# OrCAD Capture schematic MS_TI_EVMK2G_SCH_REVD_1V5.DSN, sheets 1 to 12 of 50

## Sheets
1 50. OVER VOLTAGE PROTECTION: size C; title: OVER VOLTAGE PROTECTION
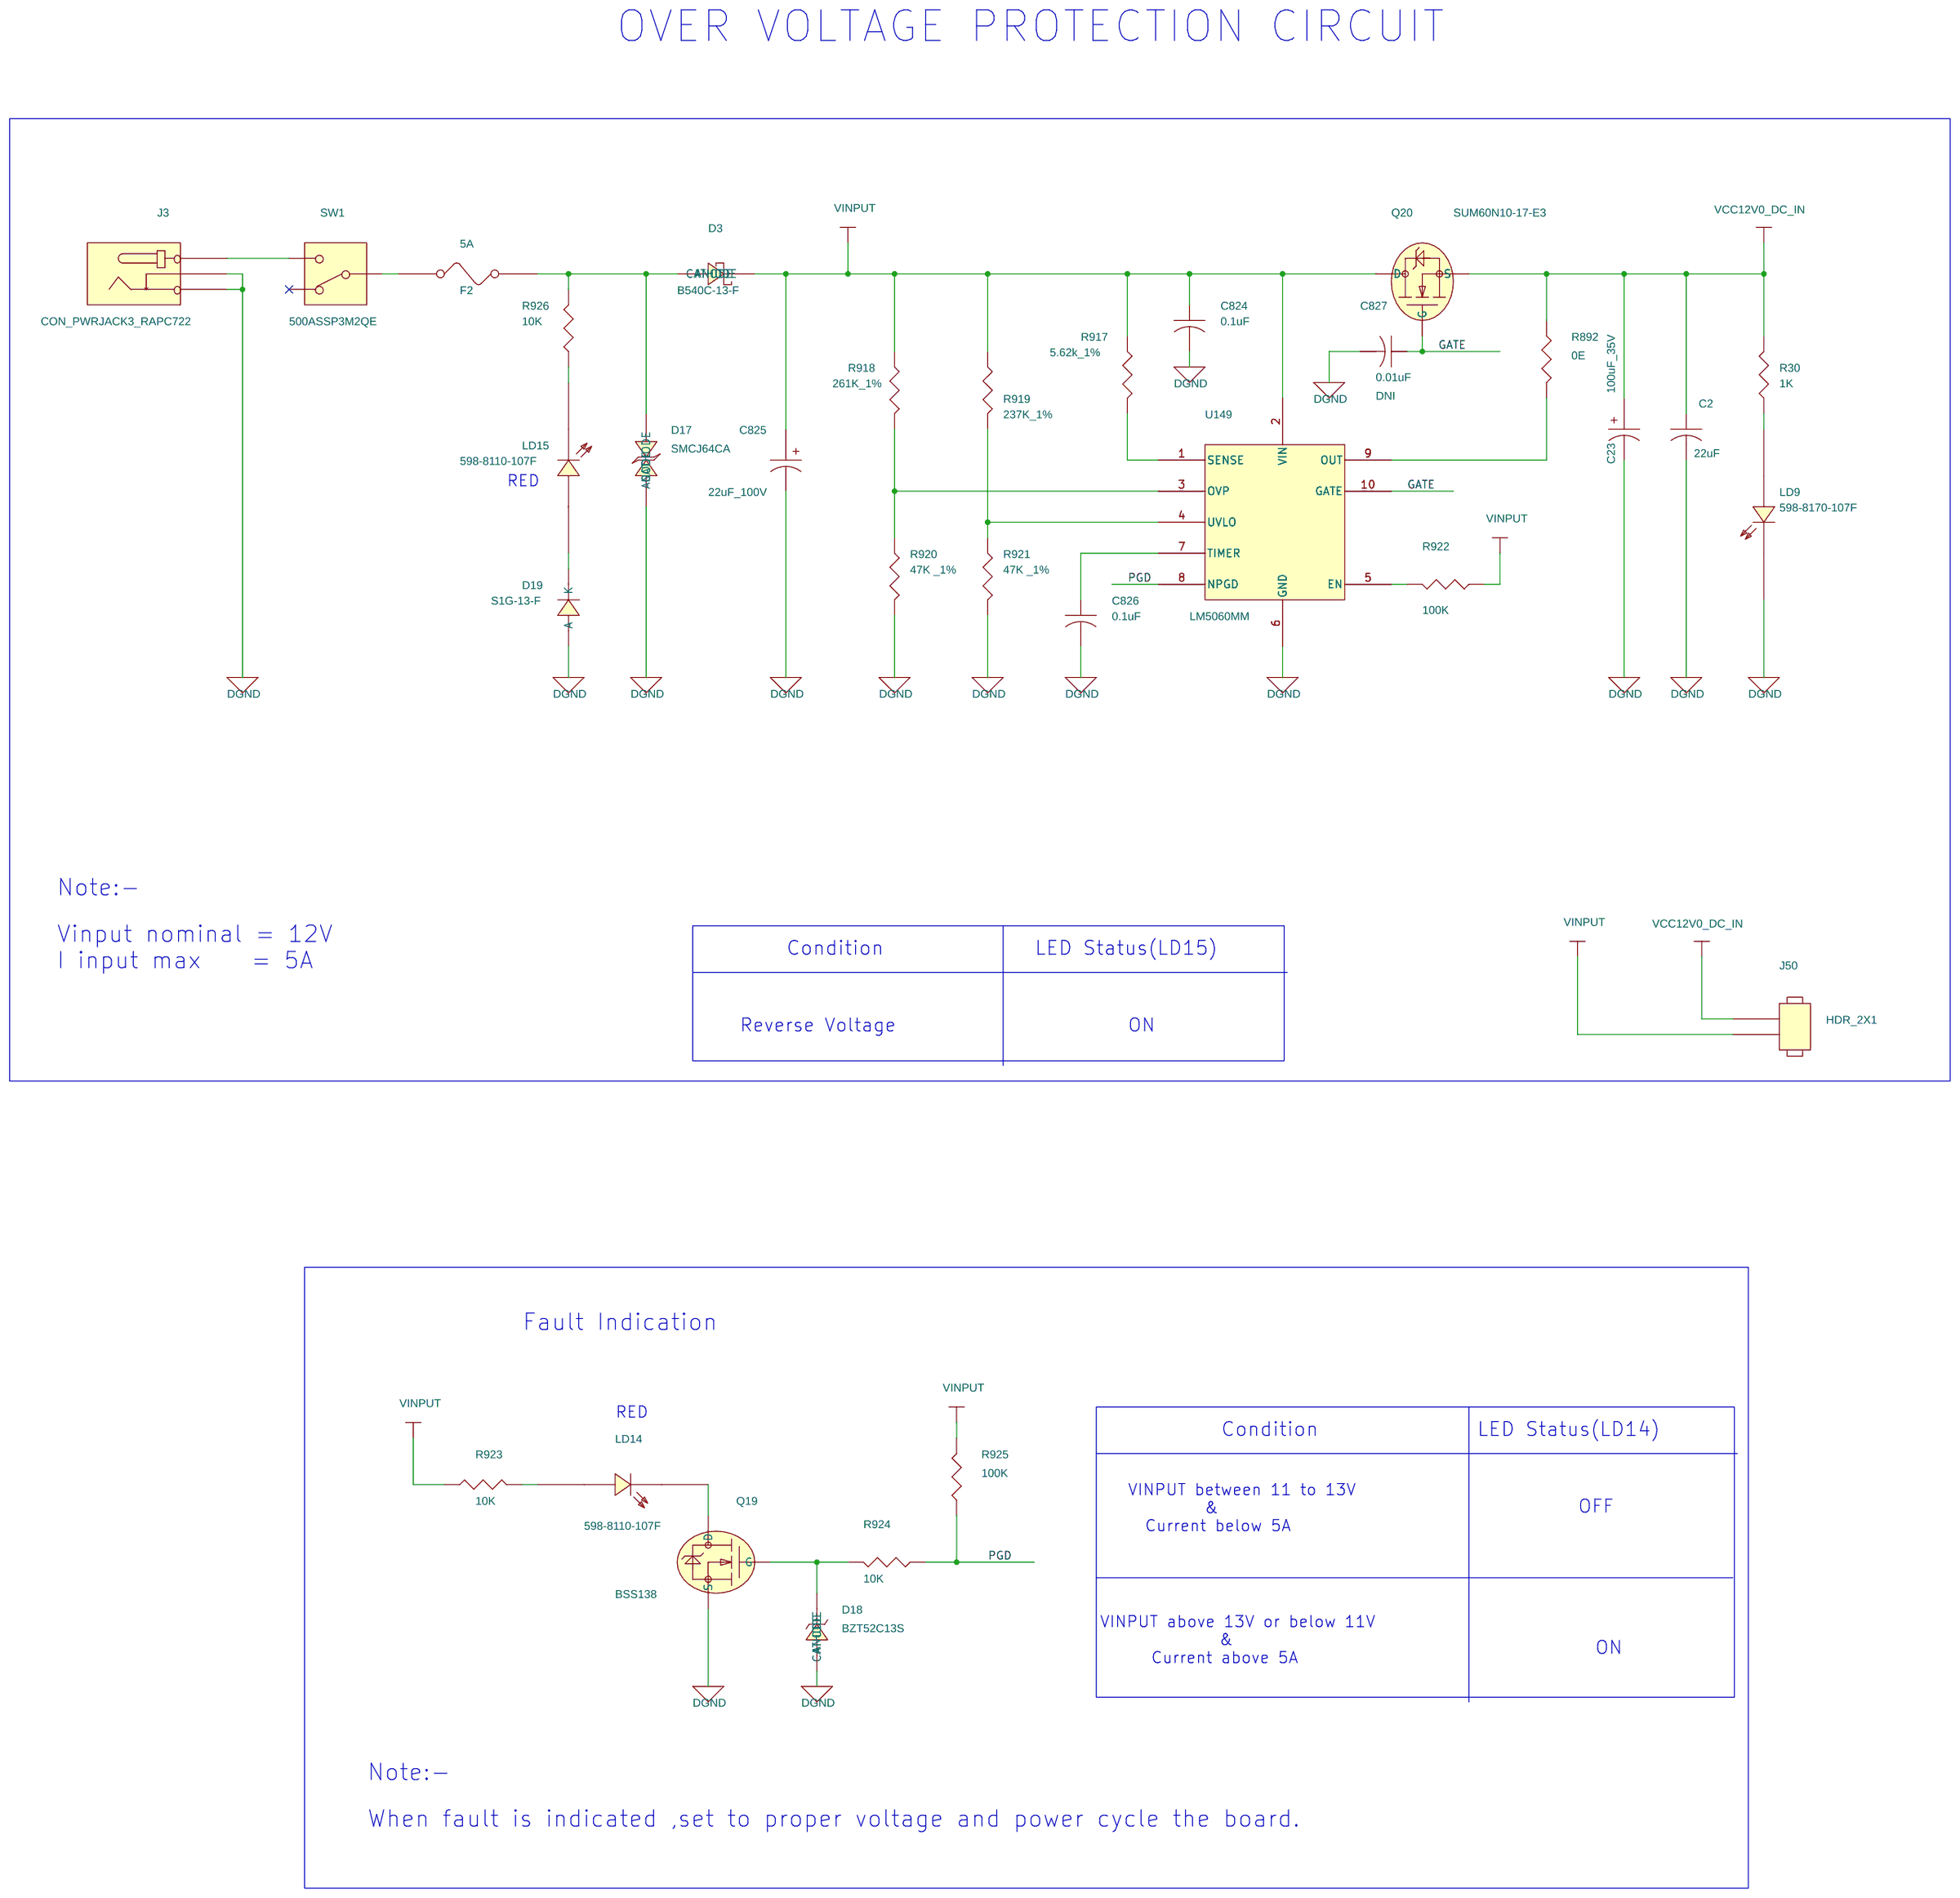
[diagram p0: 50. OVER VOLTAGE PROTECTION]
2 01. TABLE OF CONTENTS: title: TABLE OF CONTENTS; rev: D; note: MS_TI_K2GEVM_SCH_REVD
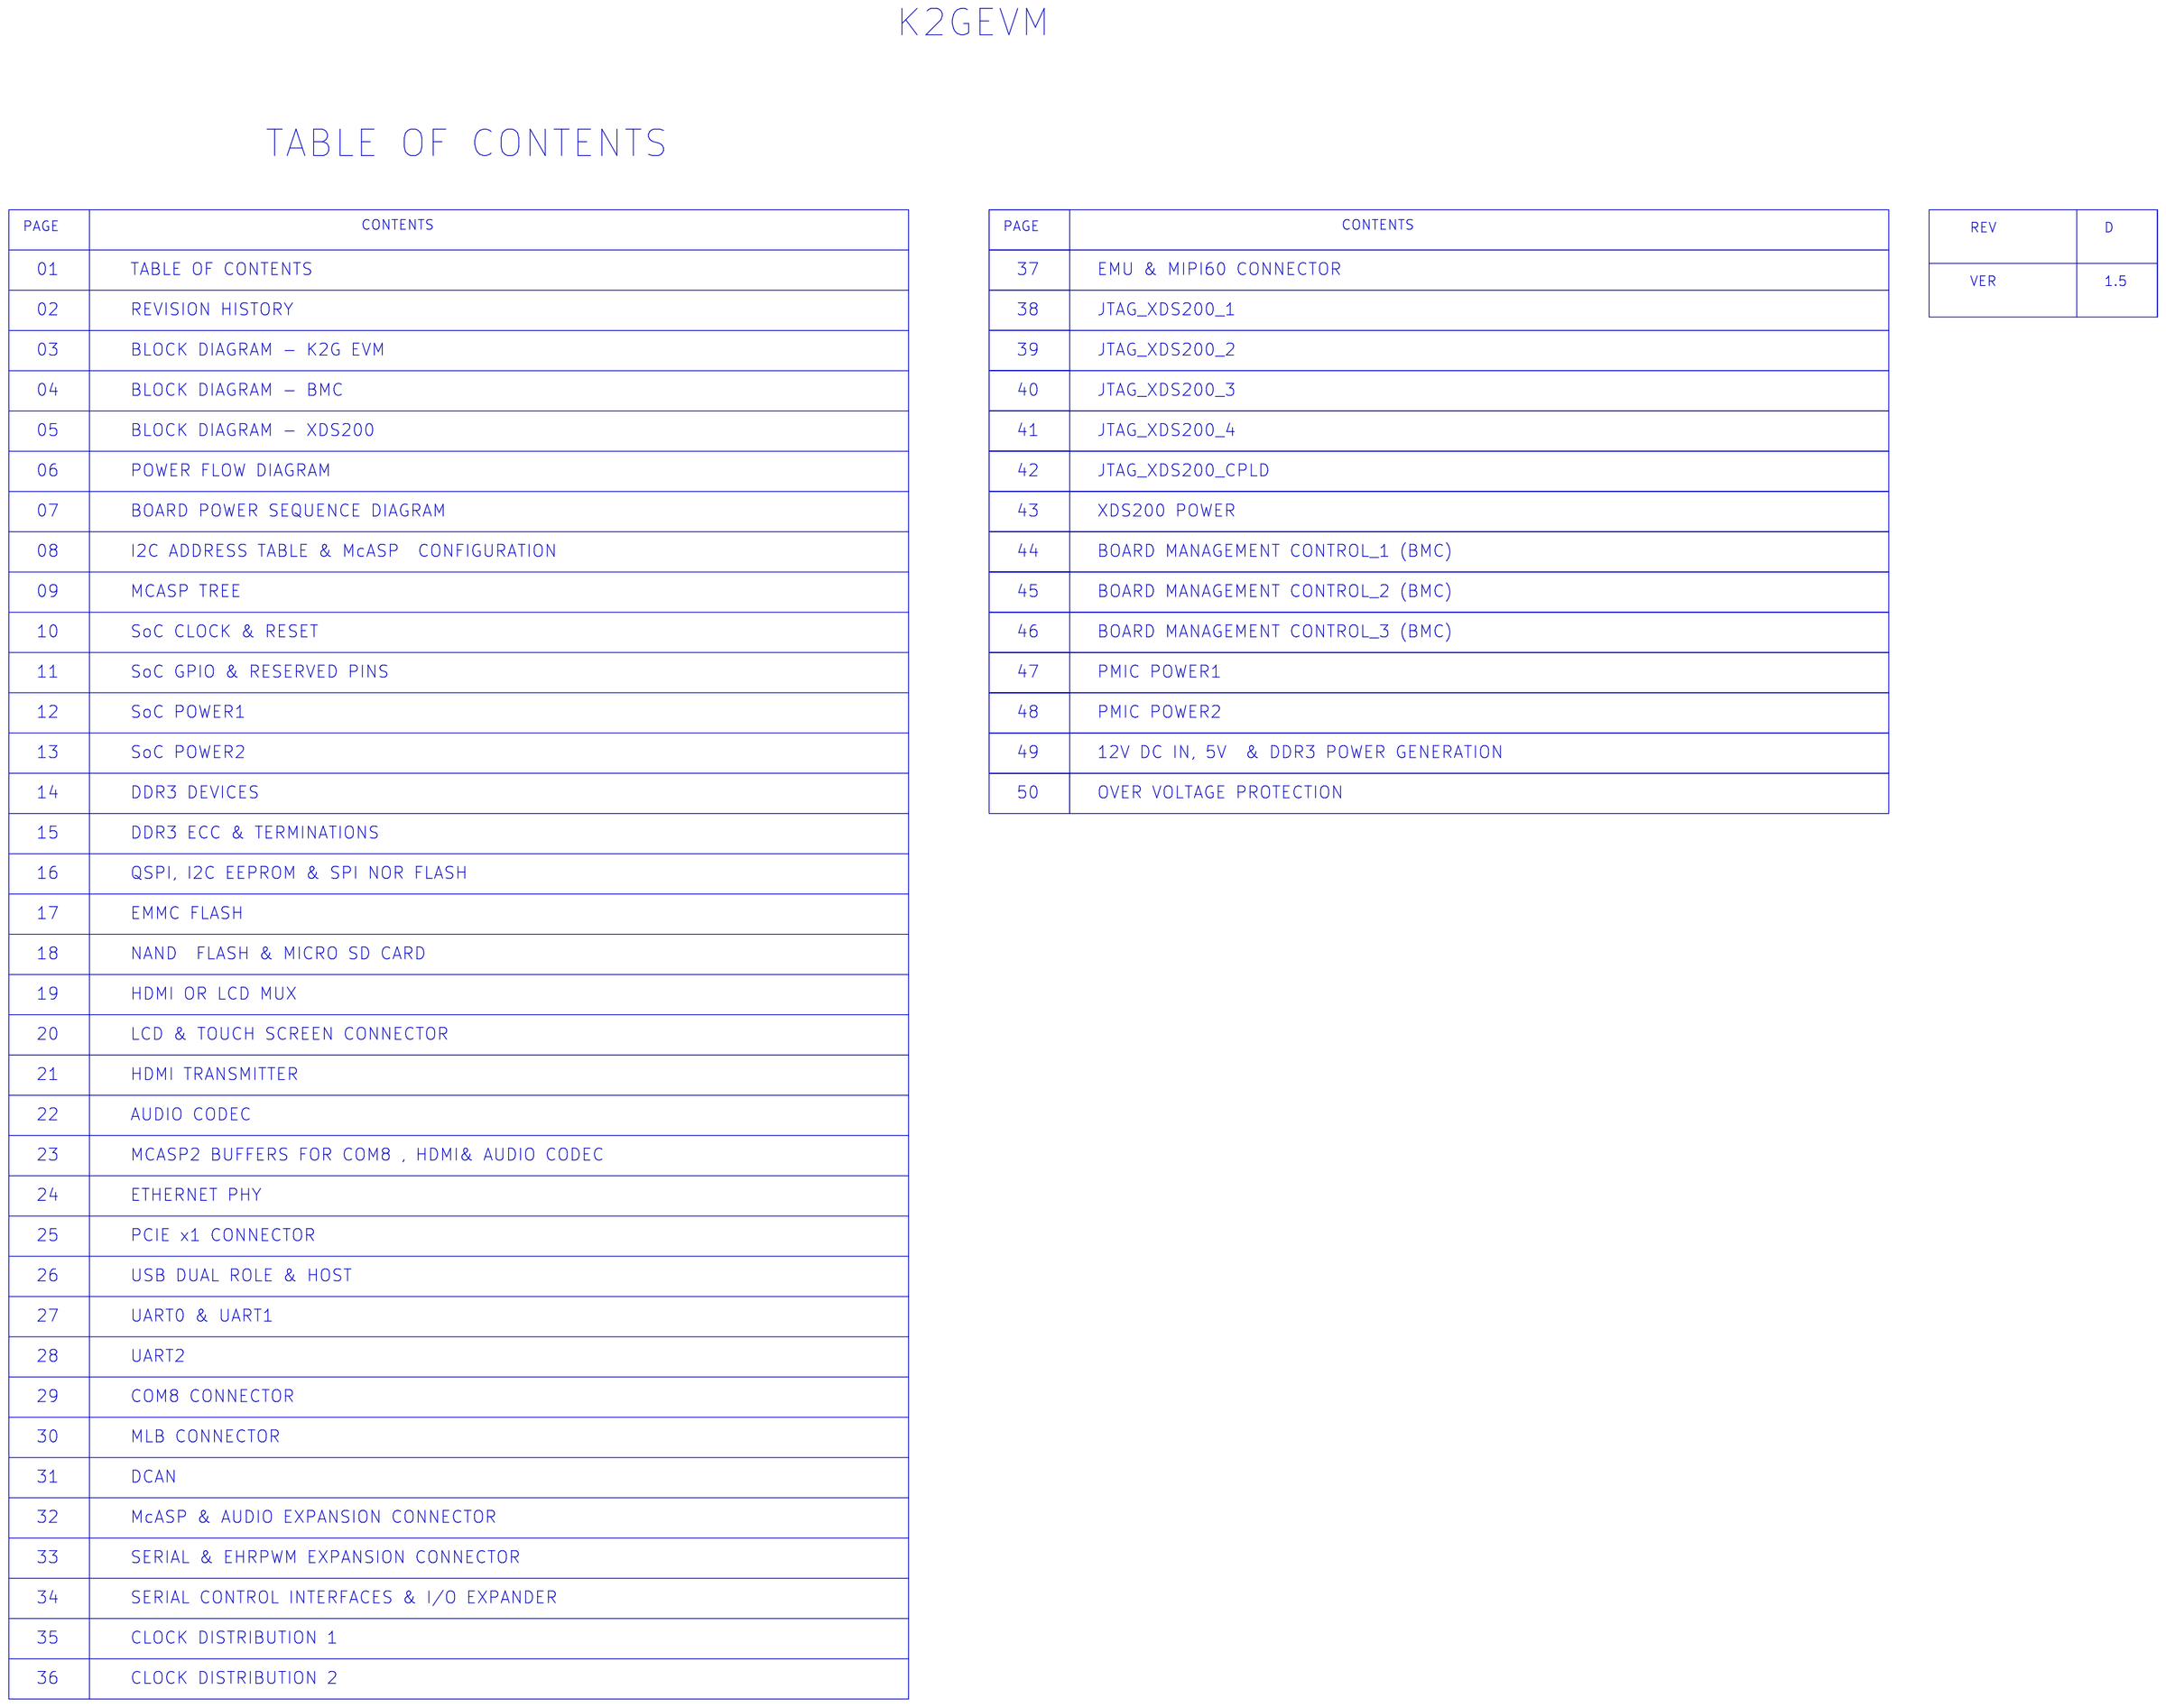
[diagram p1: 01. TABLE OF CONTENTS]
3 02. REVISION HISTORY: title: REVISION HISTORY
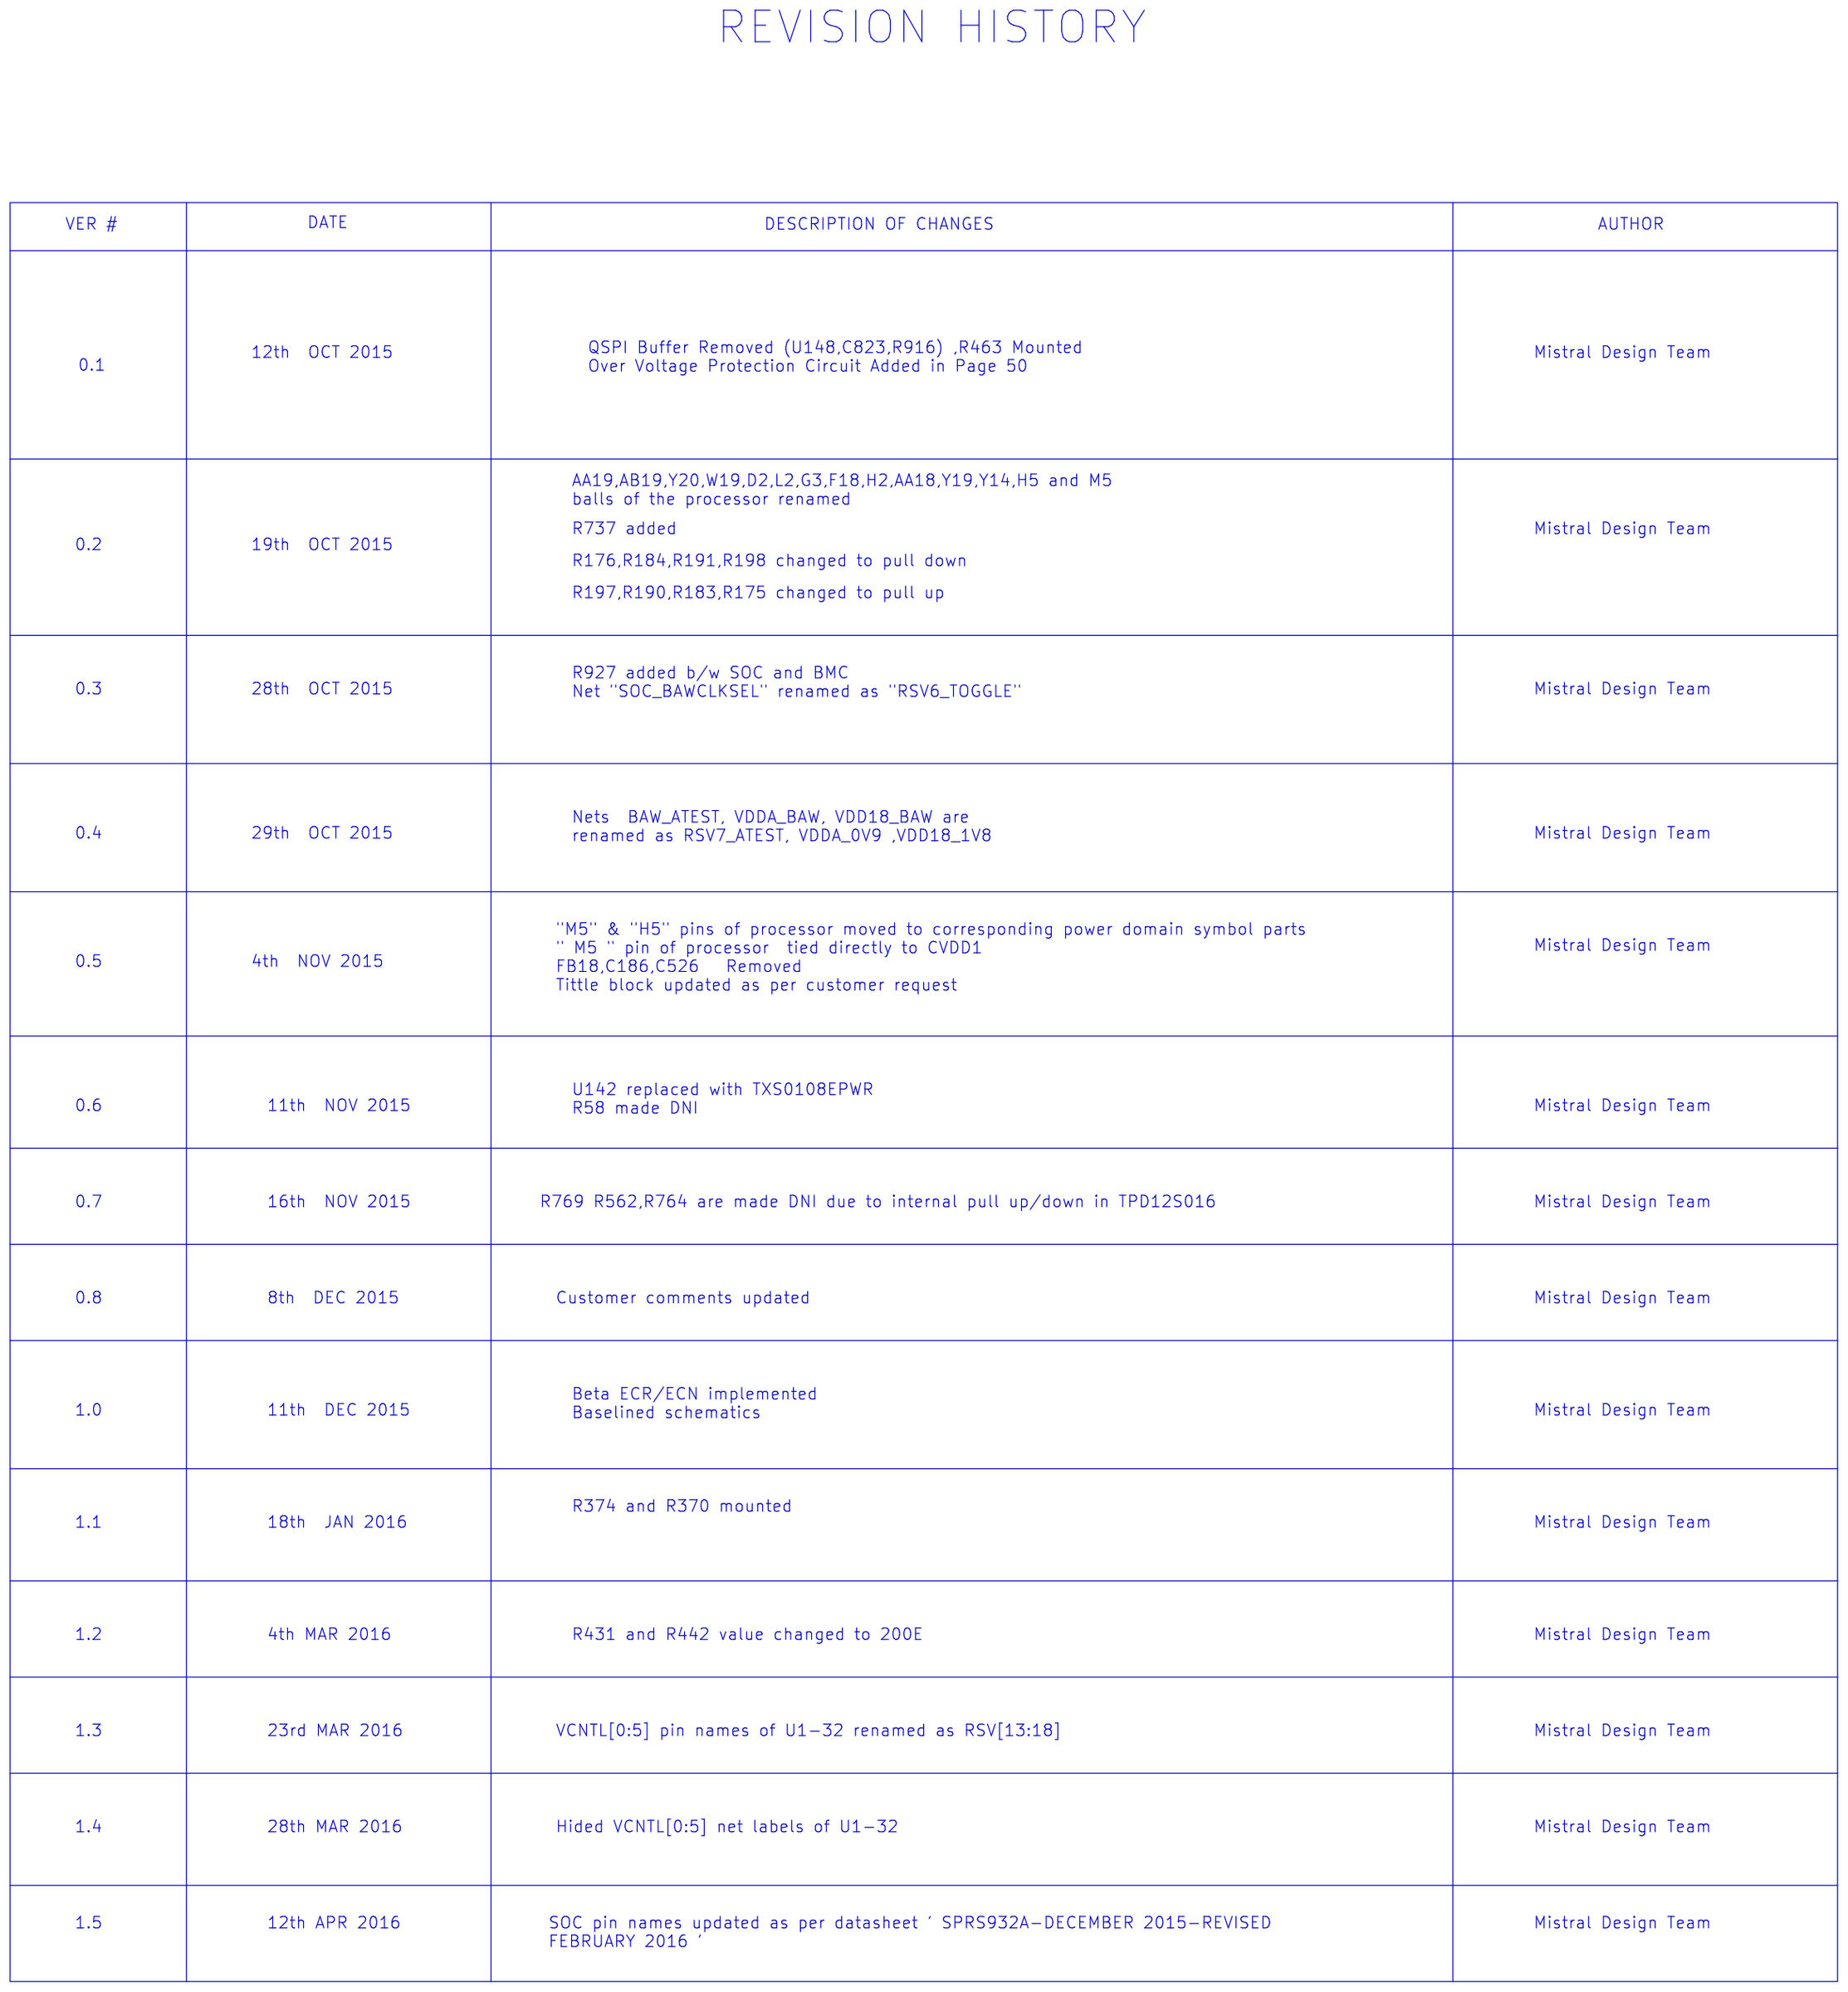
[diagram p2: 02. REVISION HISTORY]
4 03. BLOCK DIAGRAM - SoC: title: BLOCK DIAGRAM - K2G EVM
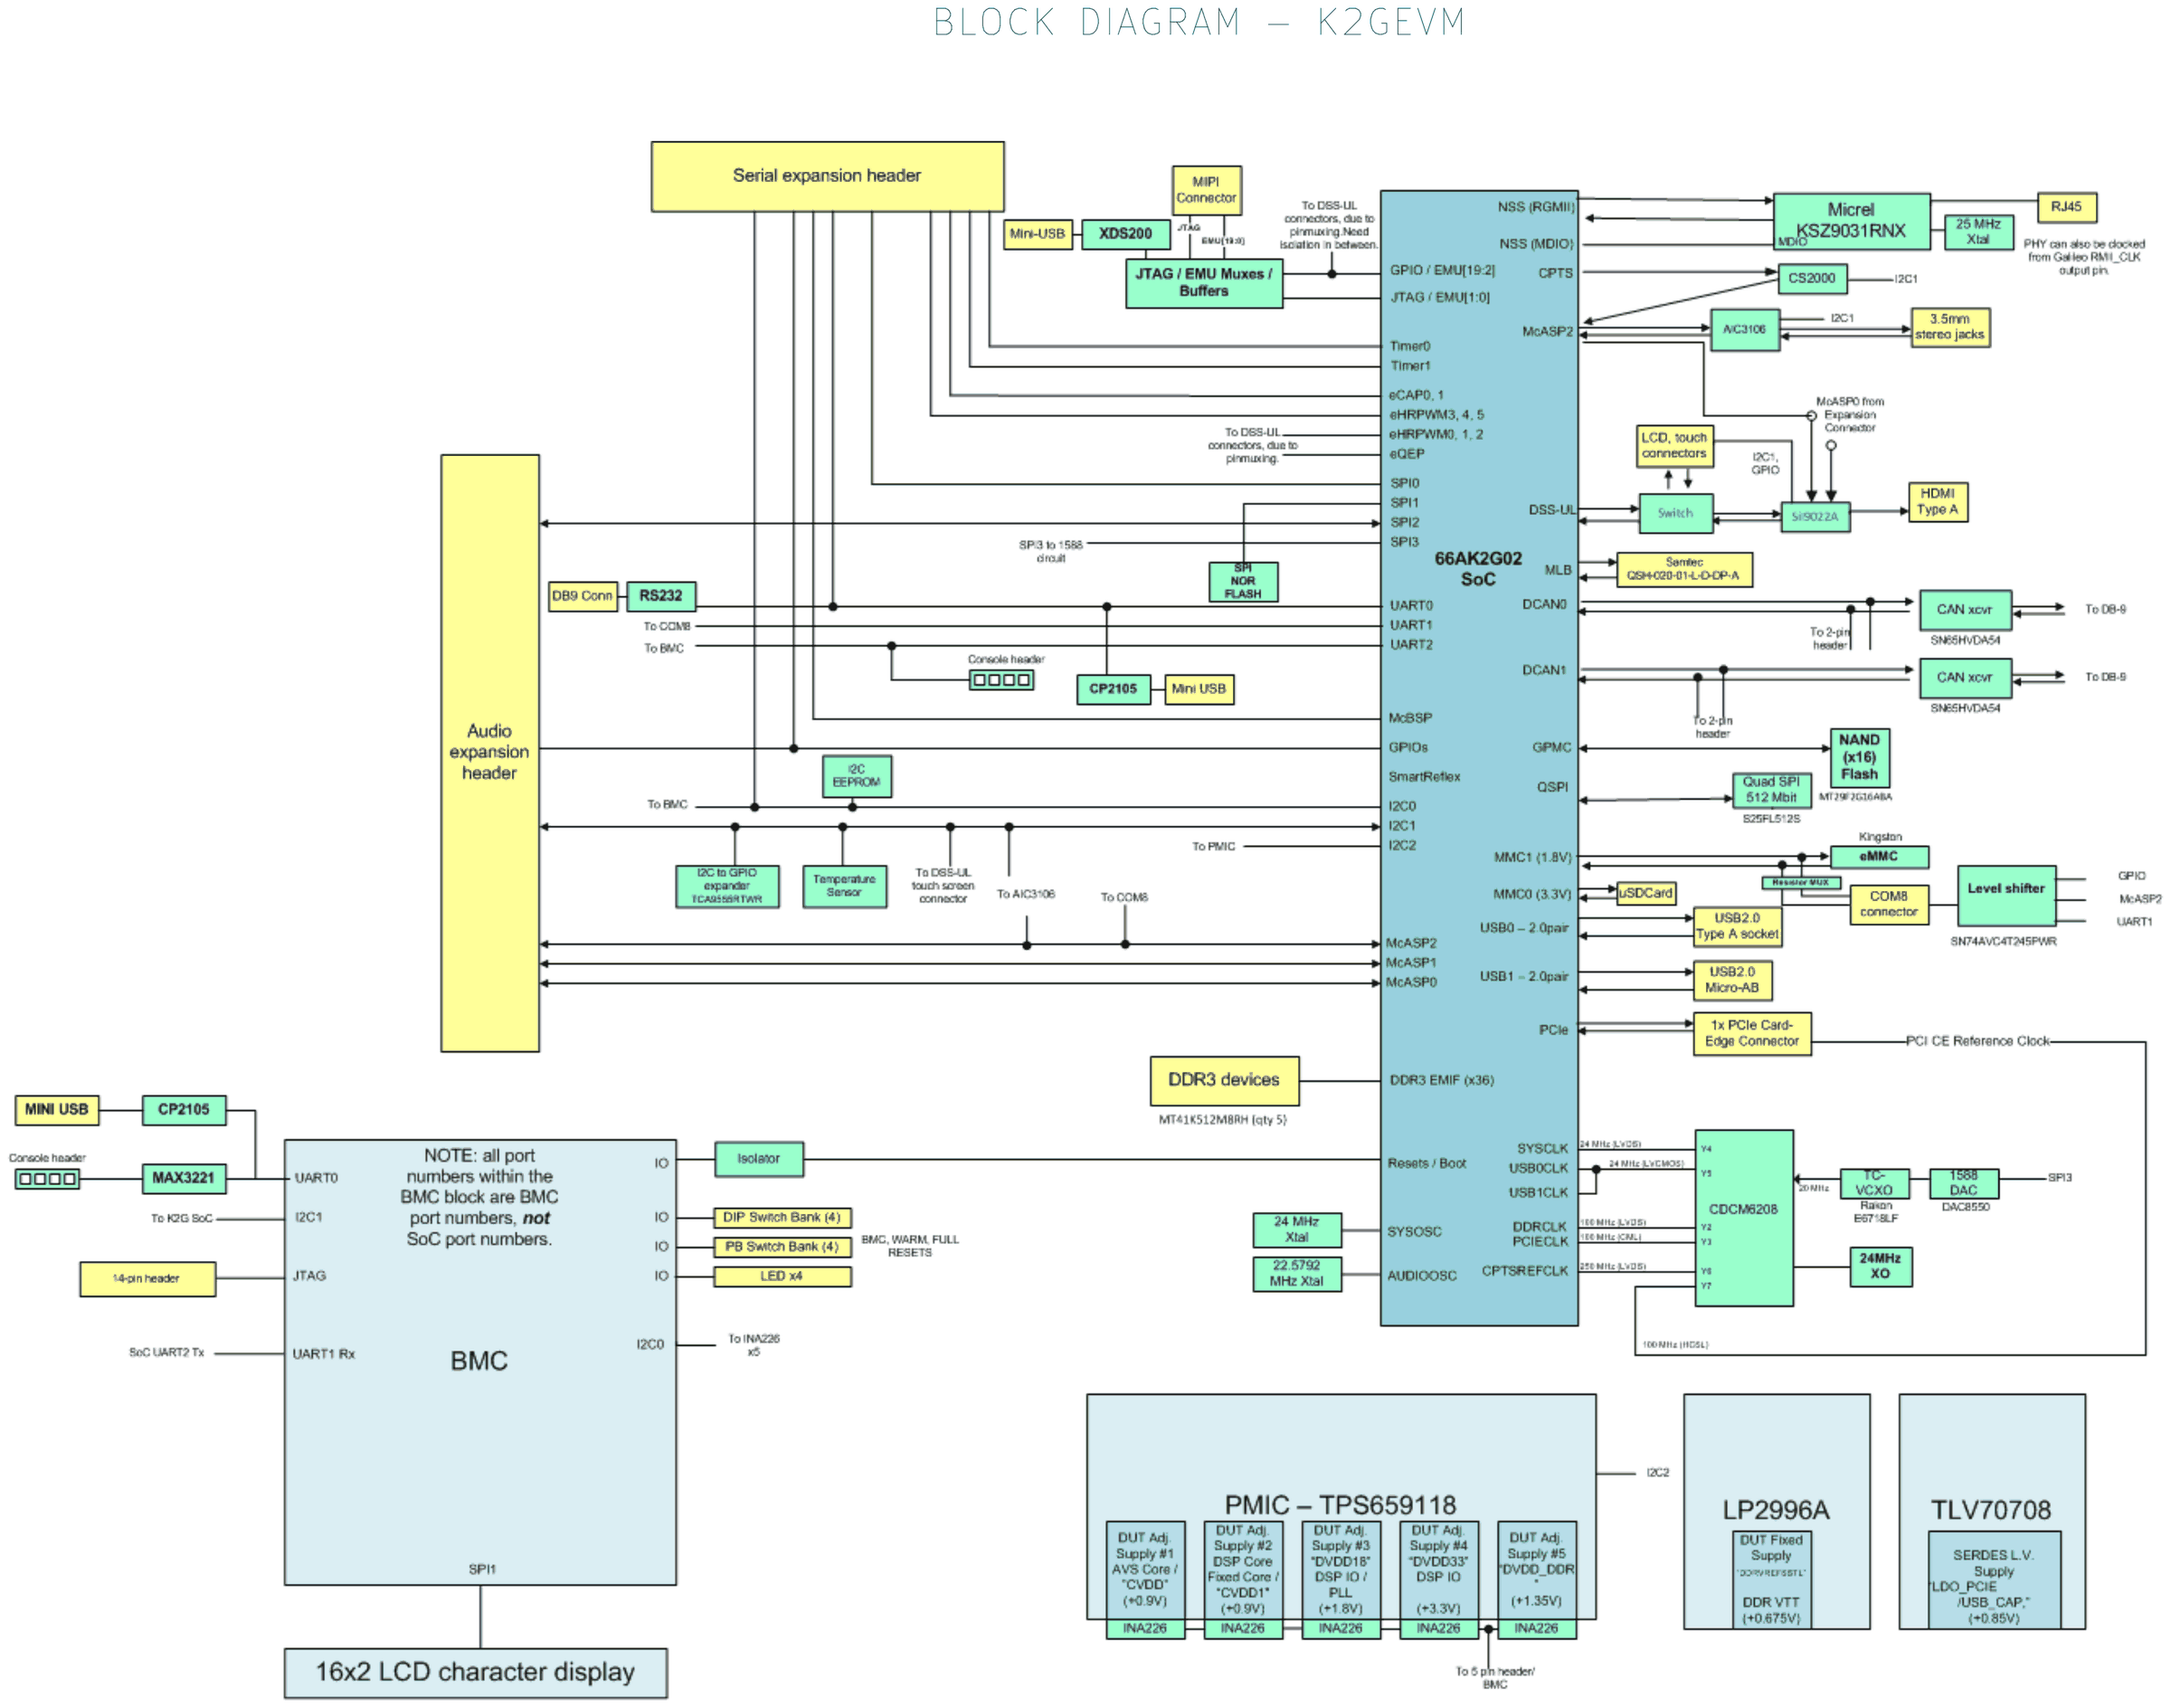
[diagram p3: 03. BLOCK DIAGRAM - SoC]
5 04. BLOCK DIAGRAM- BMC: title: BLOCK DIAGRAM - BMC
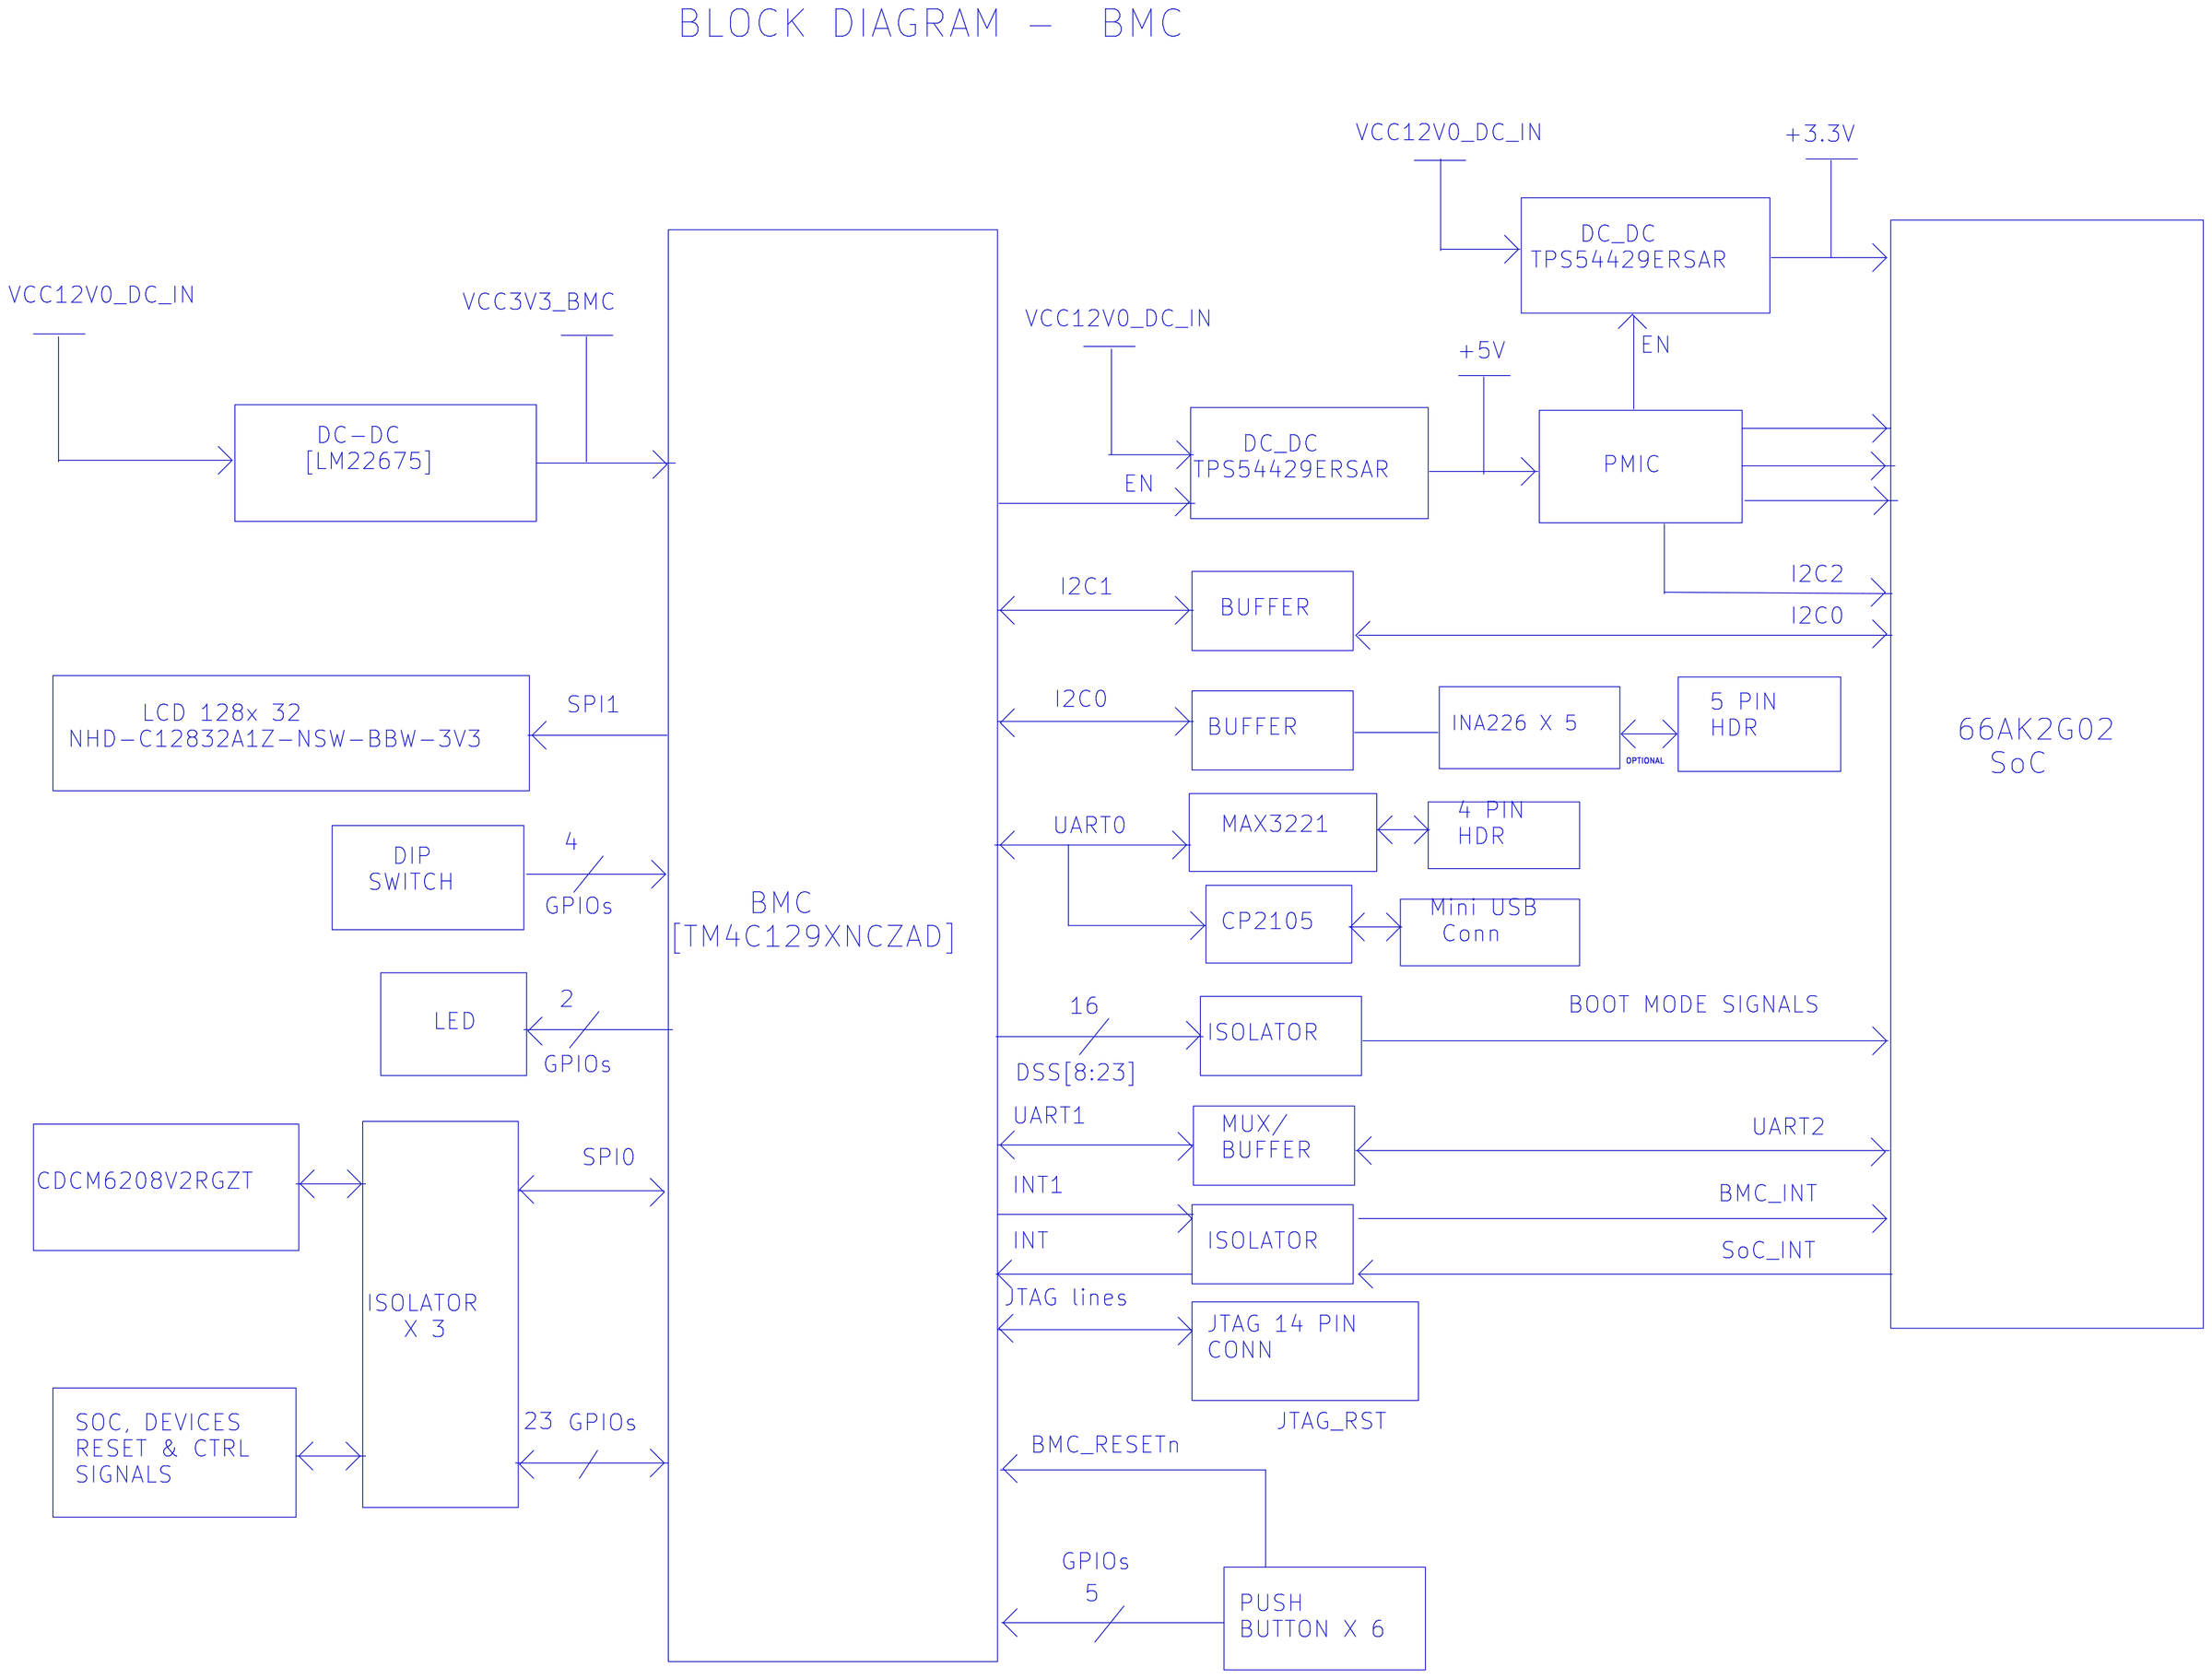
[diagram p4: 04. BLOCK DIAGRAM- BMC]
6 05. BLOCK DIAGRAM - XDS200: title: BLOCK DIAGRAM - XDS200
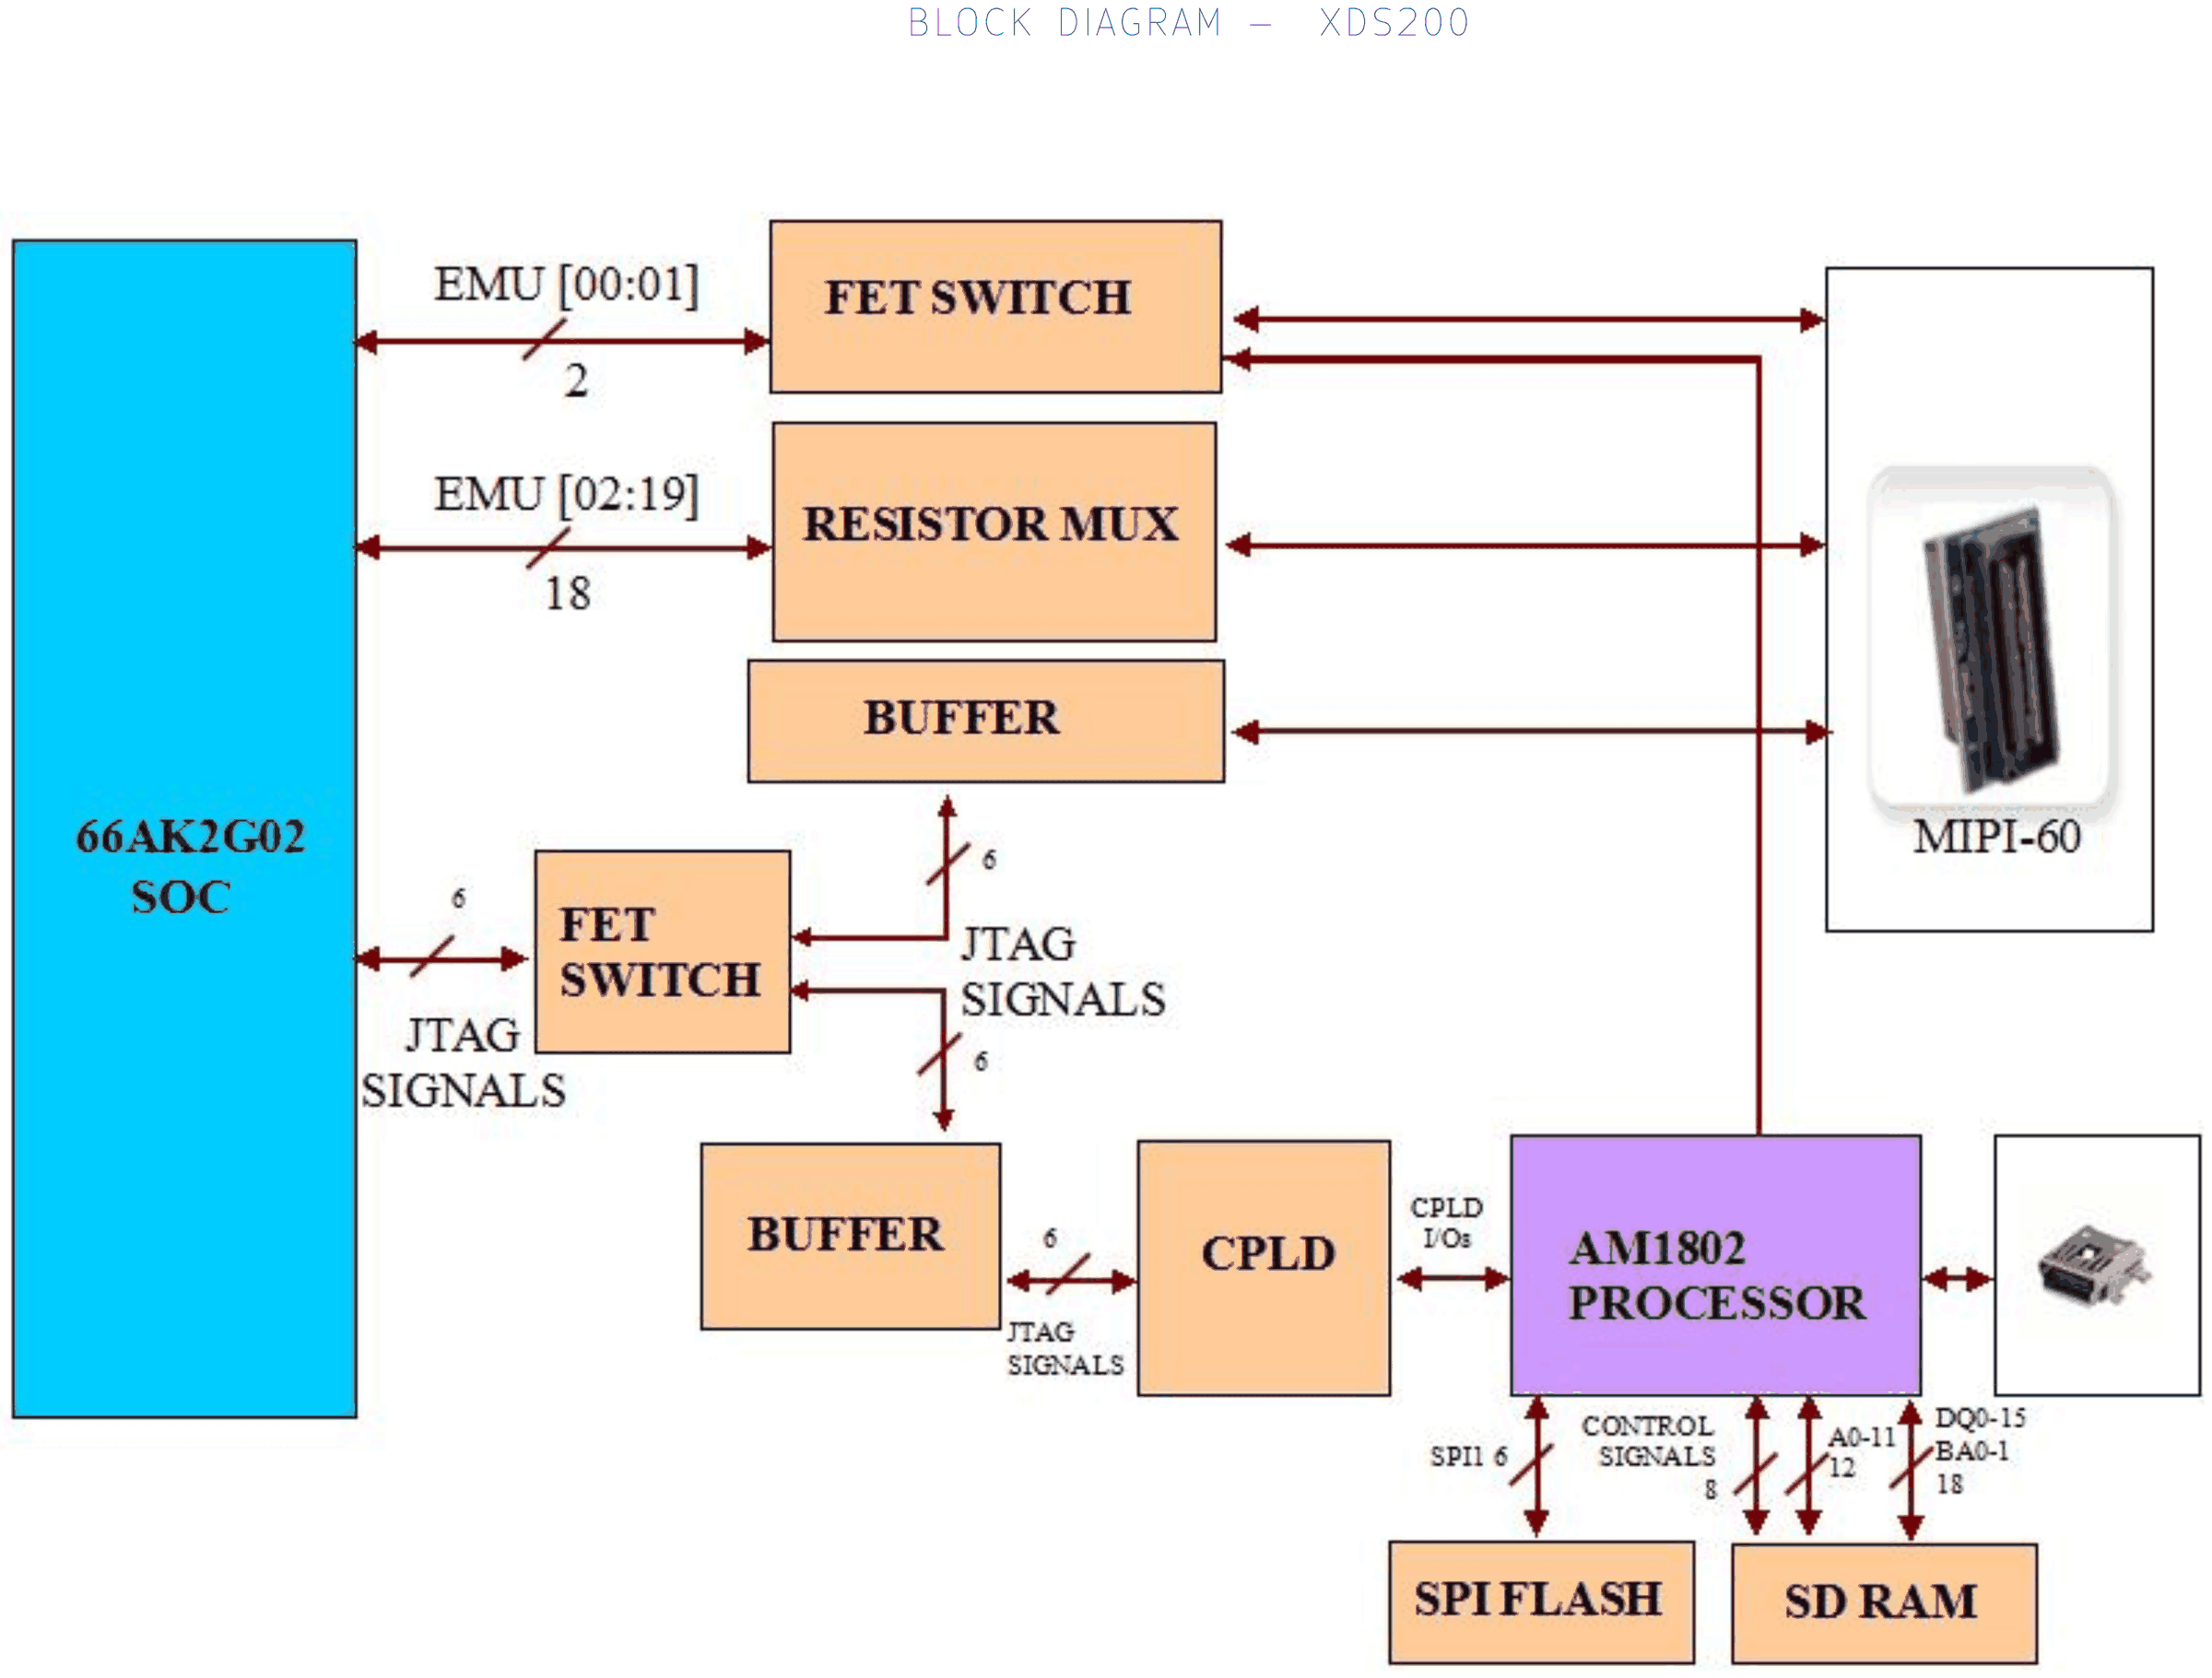
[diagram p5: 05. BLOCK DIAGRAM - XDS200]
7 06. POWER FLOW DIAGRAM: title: POWER FLOW DIAGARAM
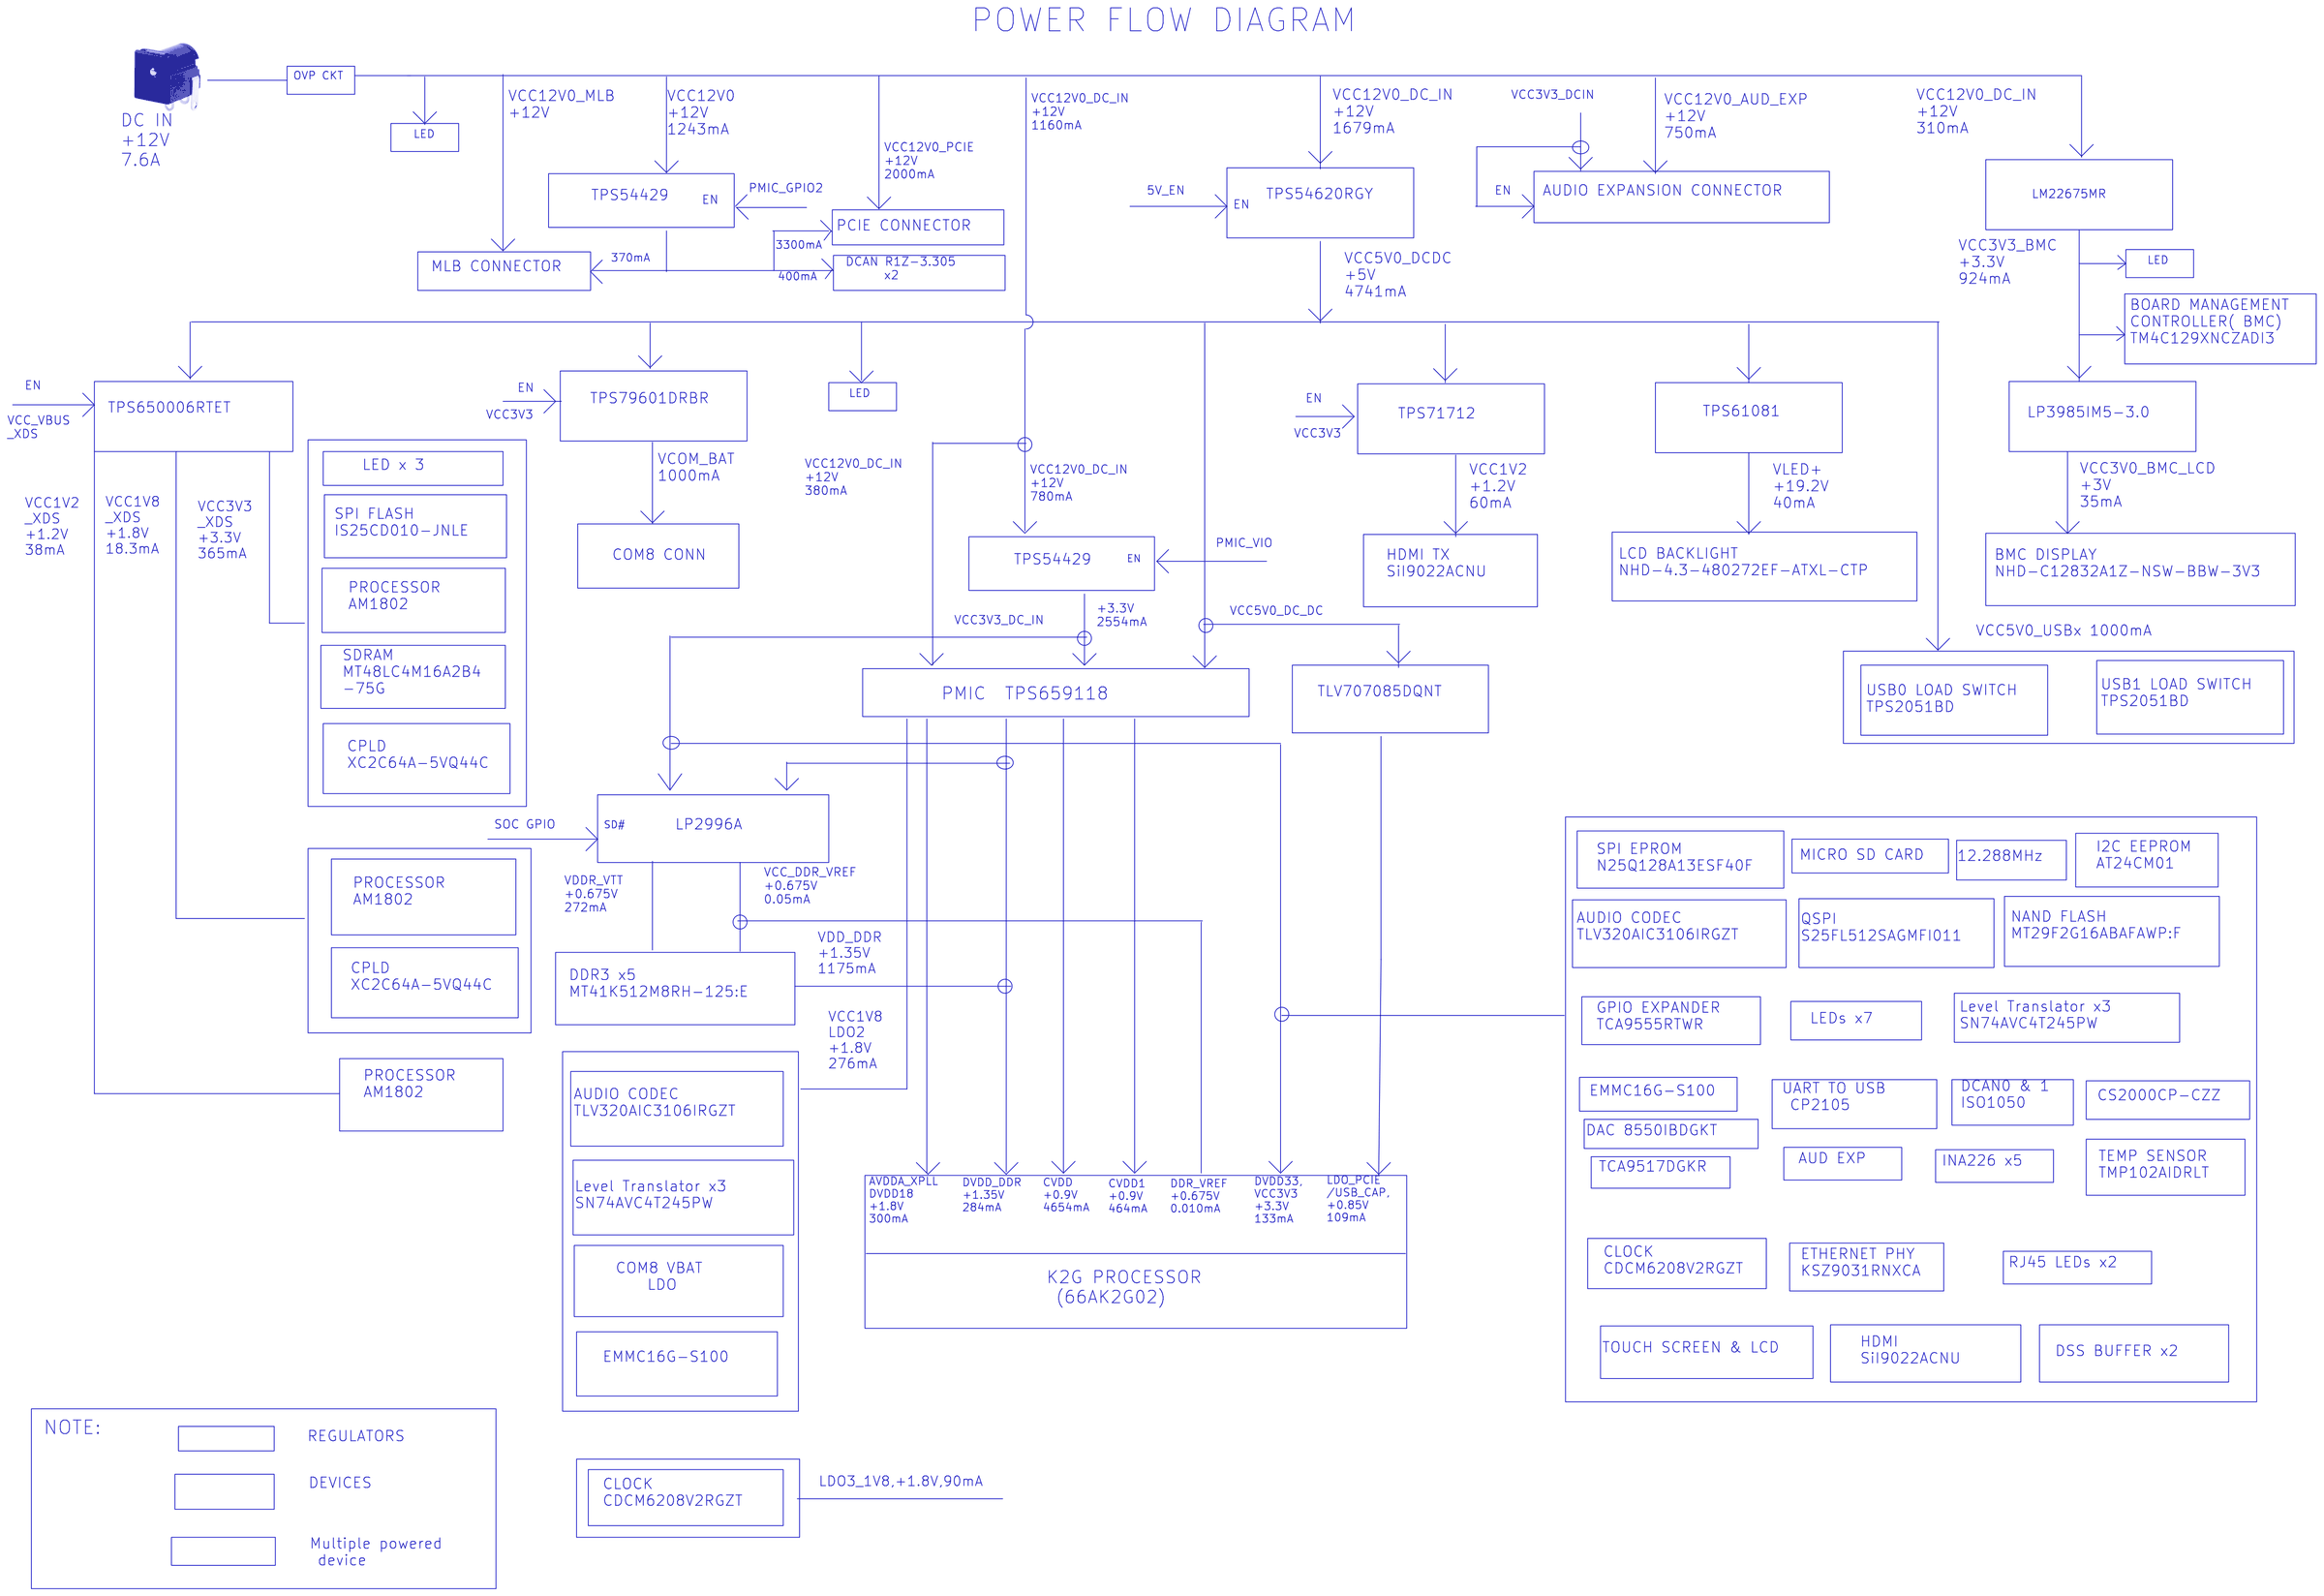
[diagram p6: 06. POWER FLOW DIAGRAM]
8 07. BOARD POWER UP SEQUENCE: title: BOARD POWER SEQUENCE DIAGARAM
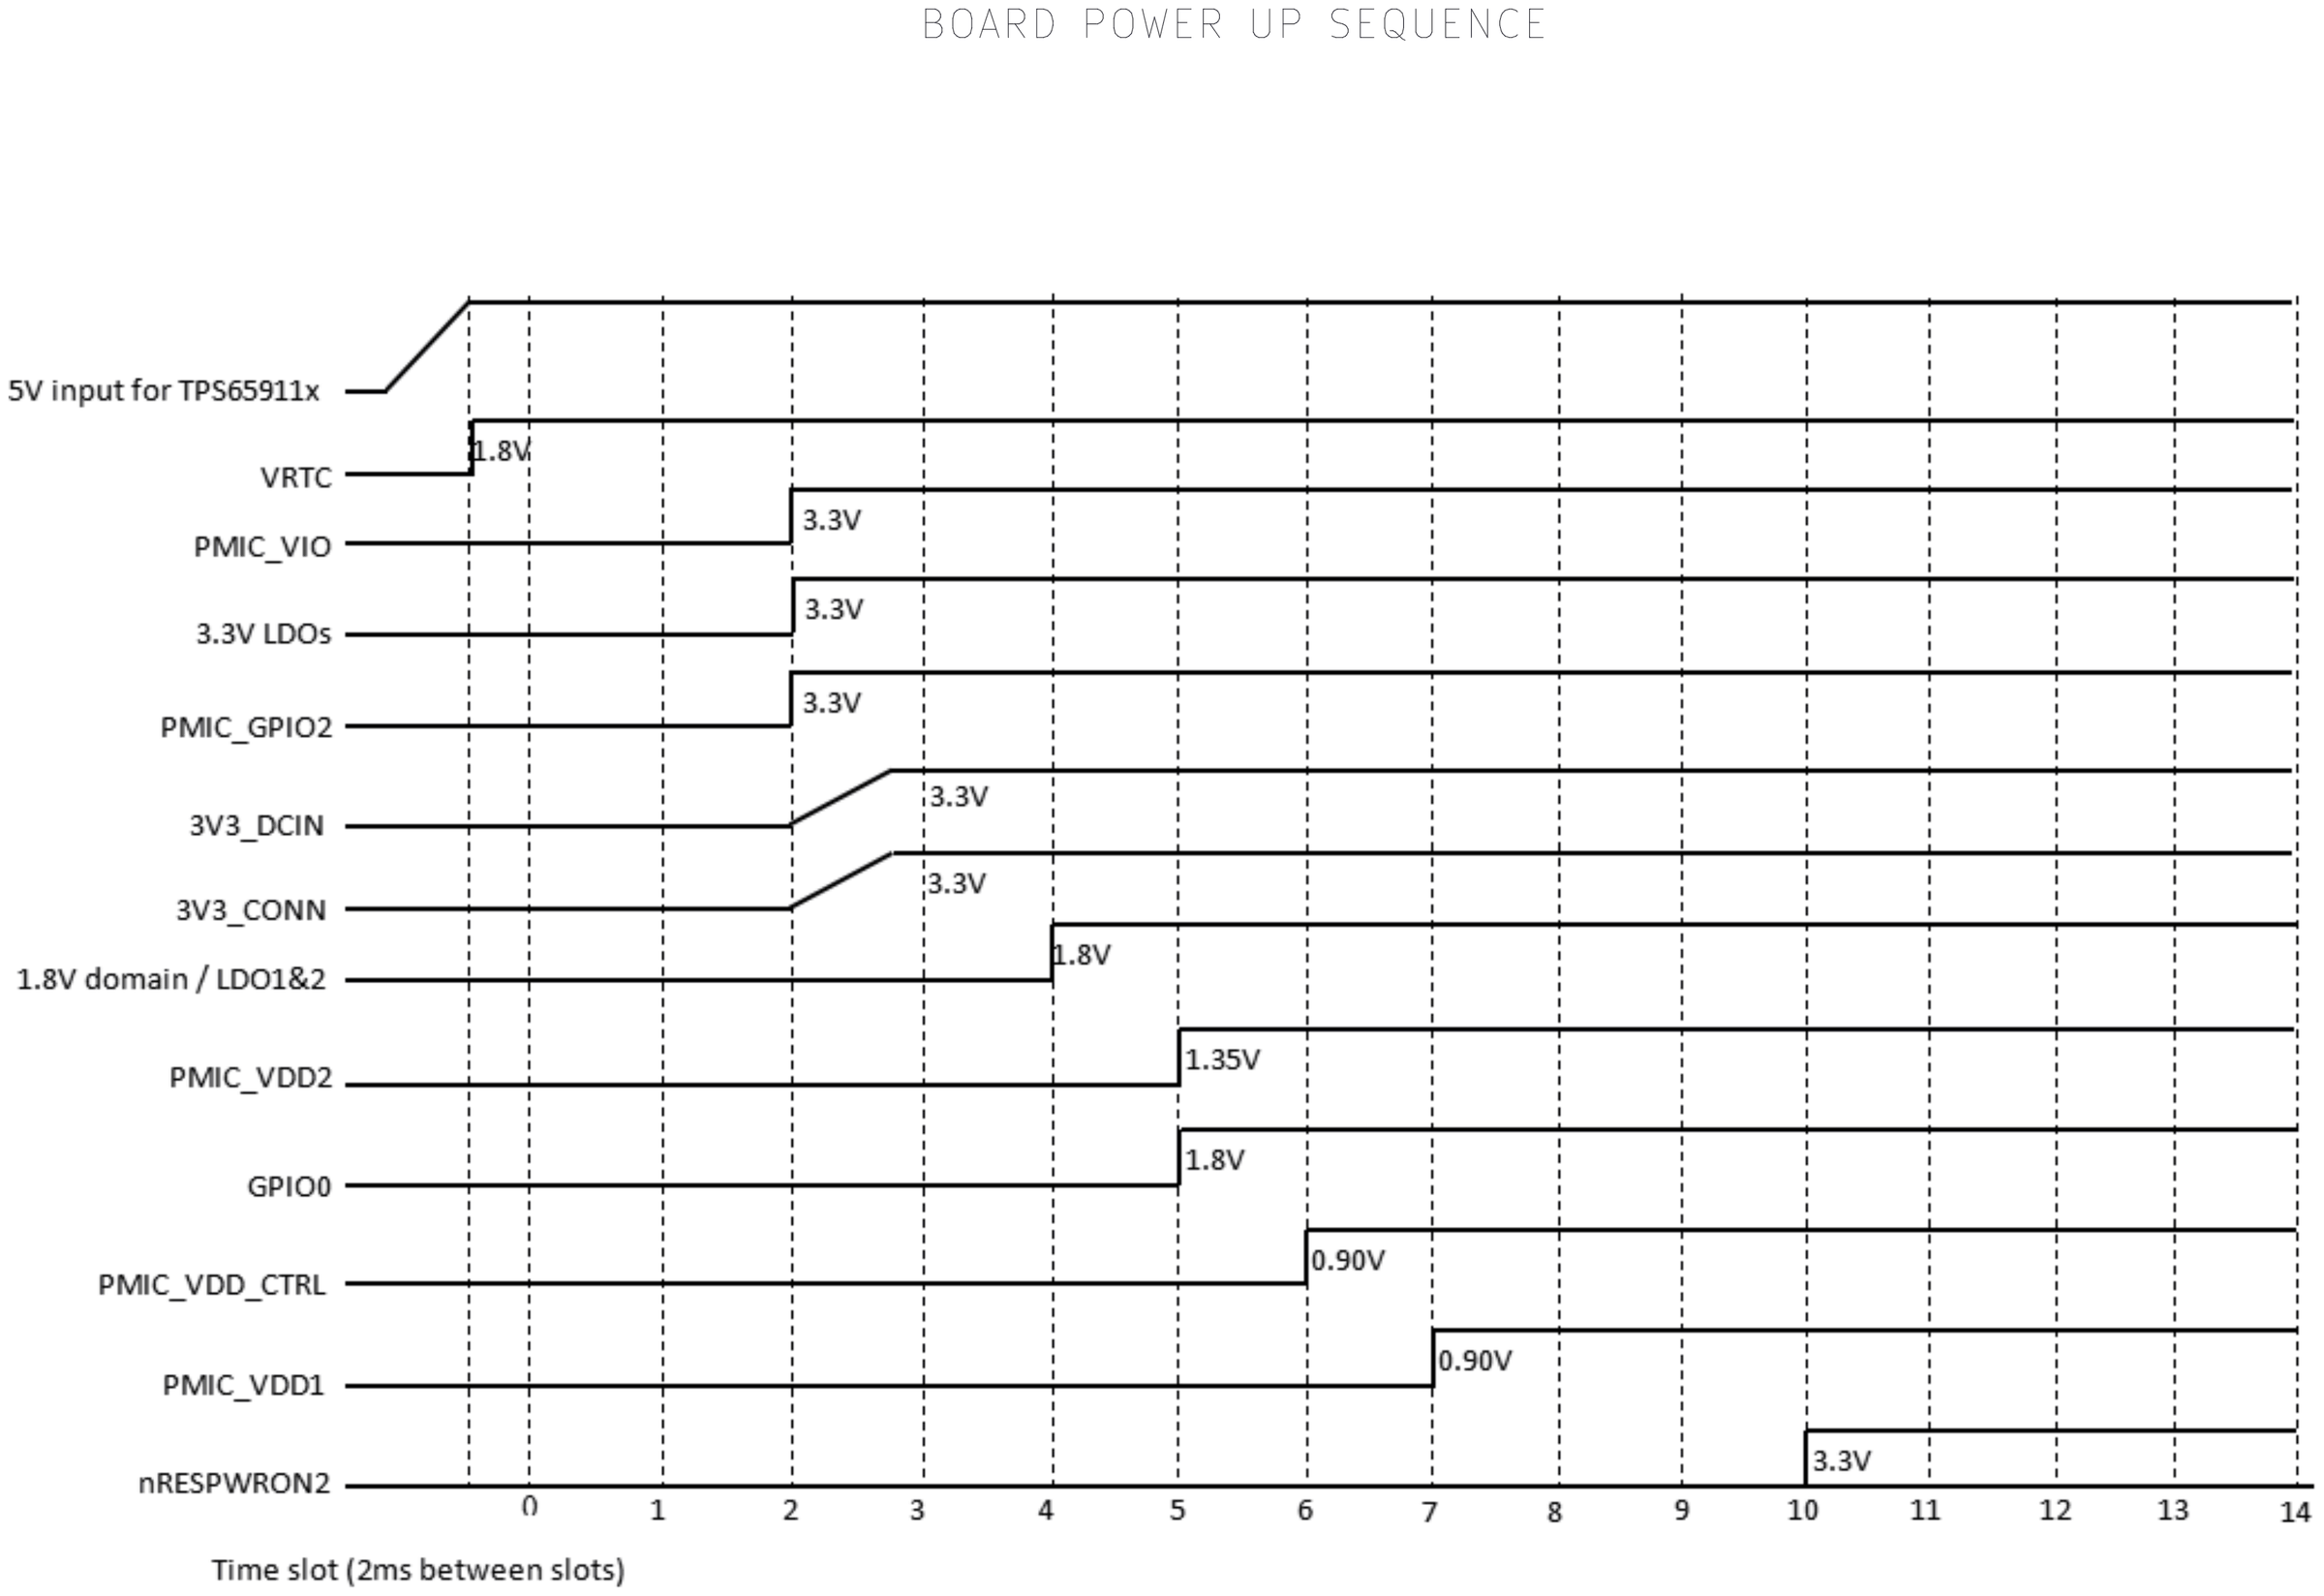
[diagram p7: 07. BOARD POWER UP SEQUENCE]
9 08. I2C TABLE: title: I2C TREE
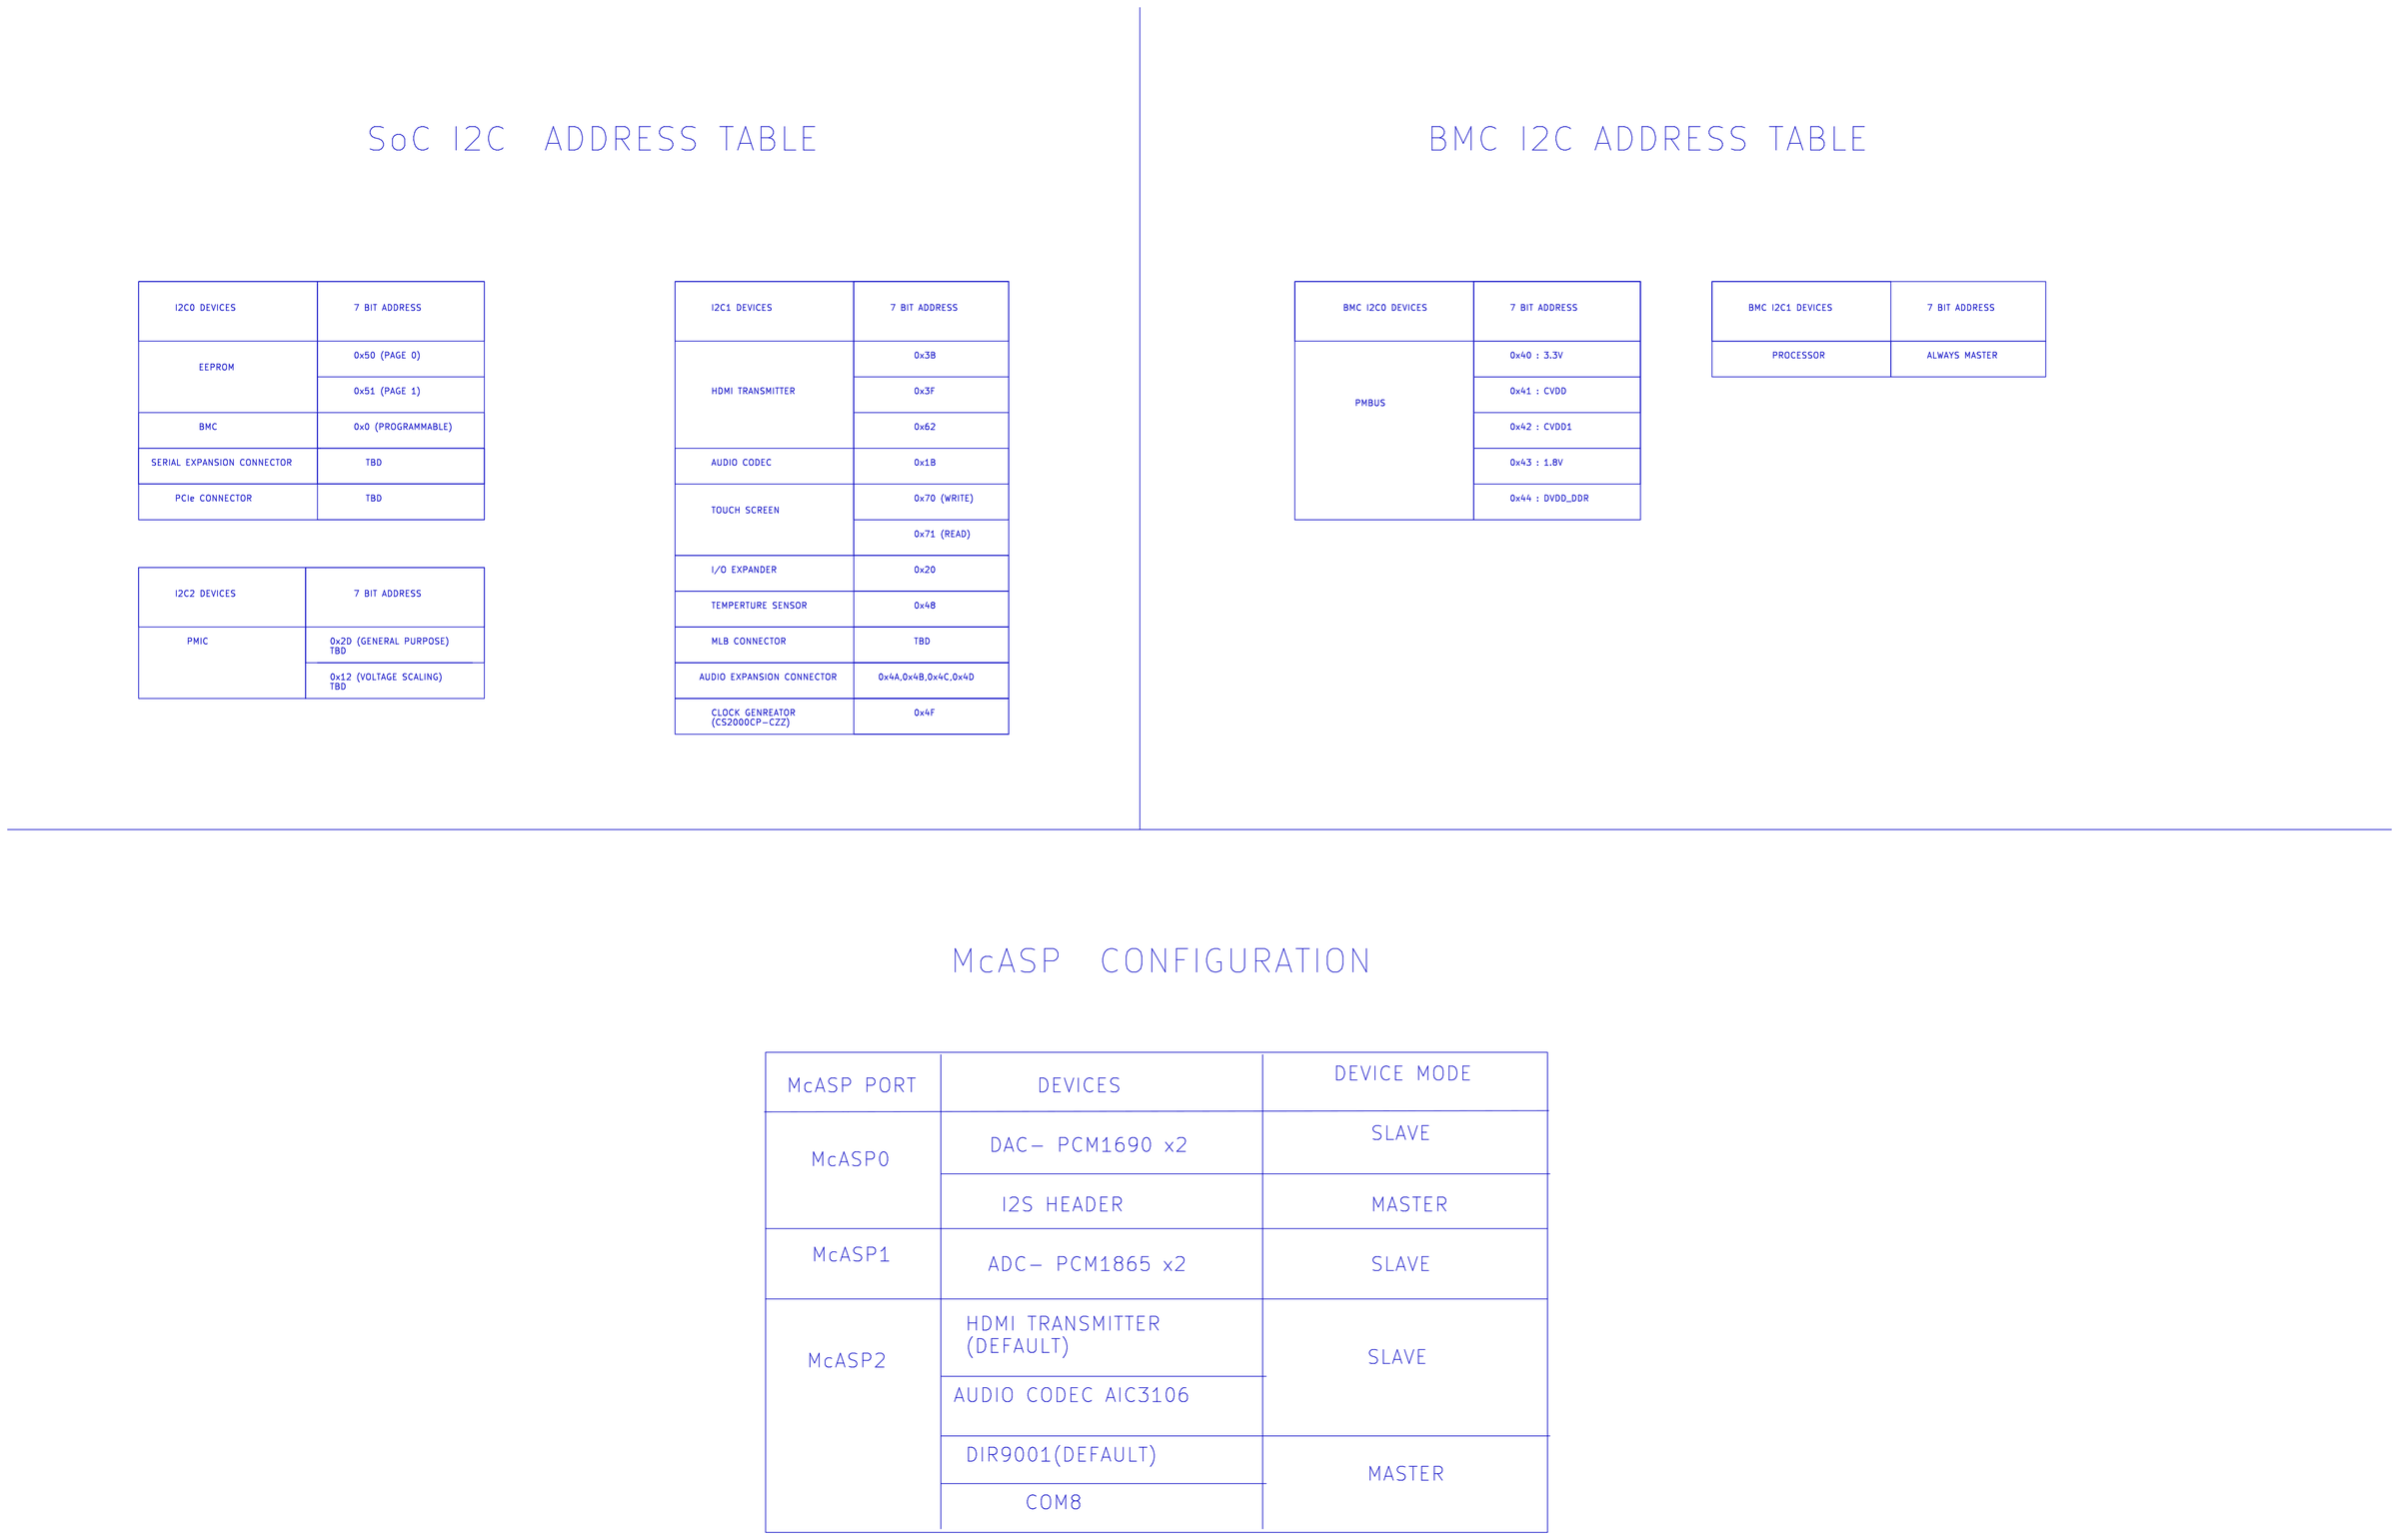
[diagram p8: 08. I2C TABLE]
10 09. MCASP TREE: title: MCASP TREE
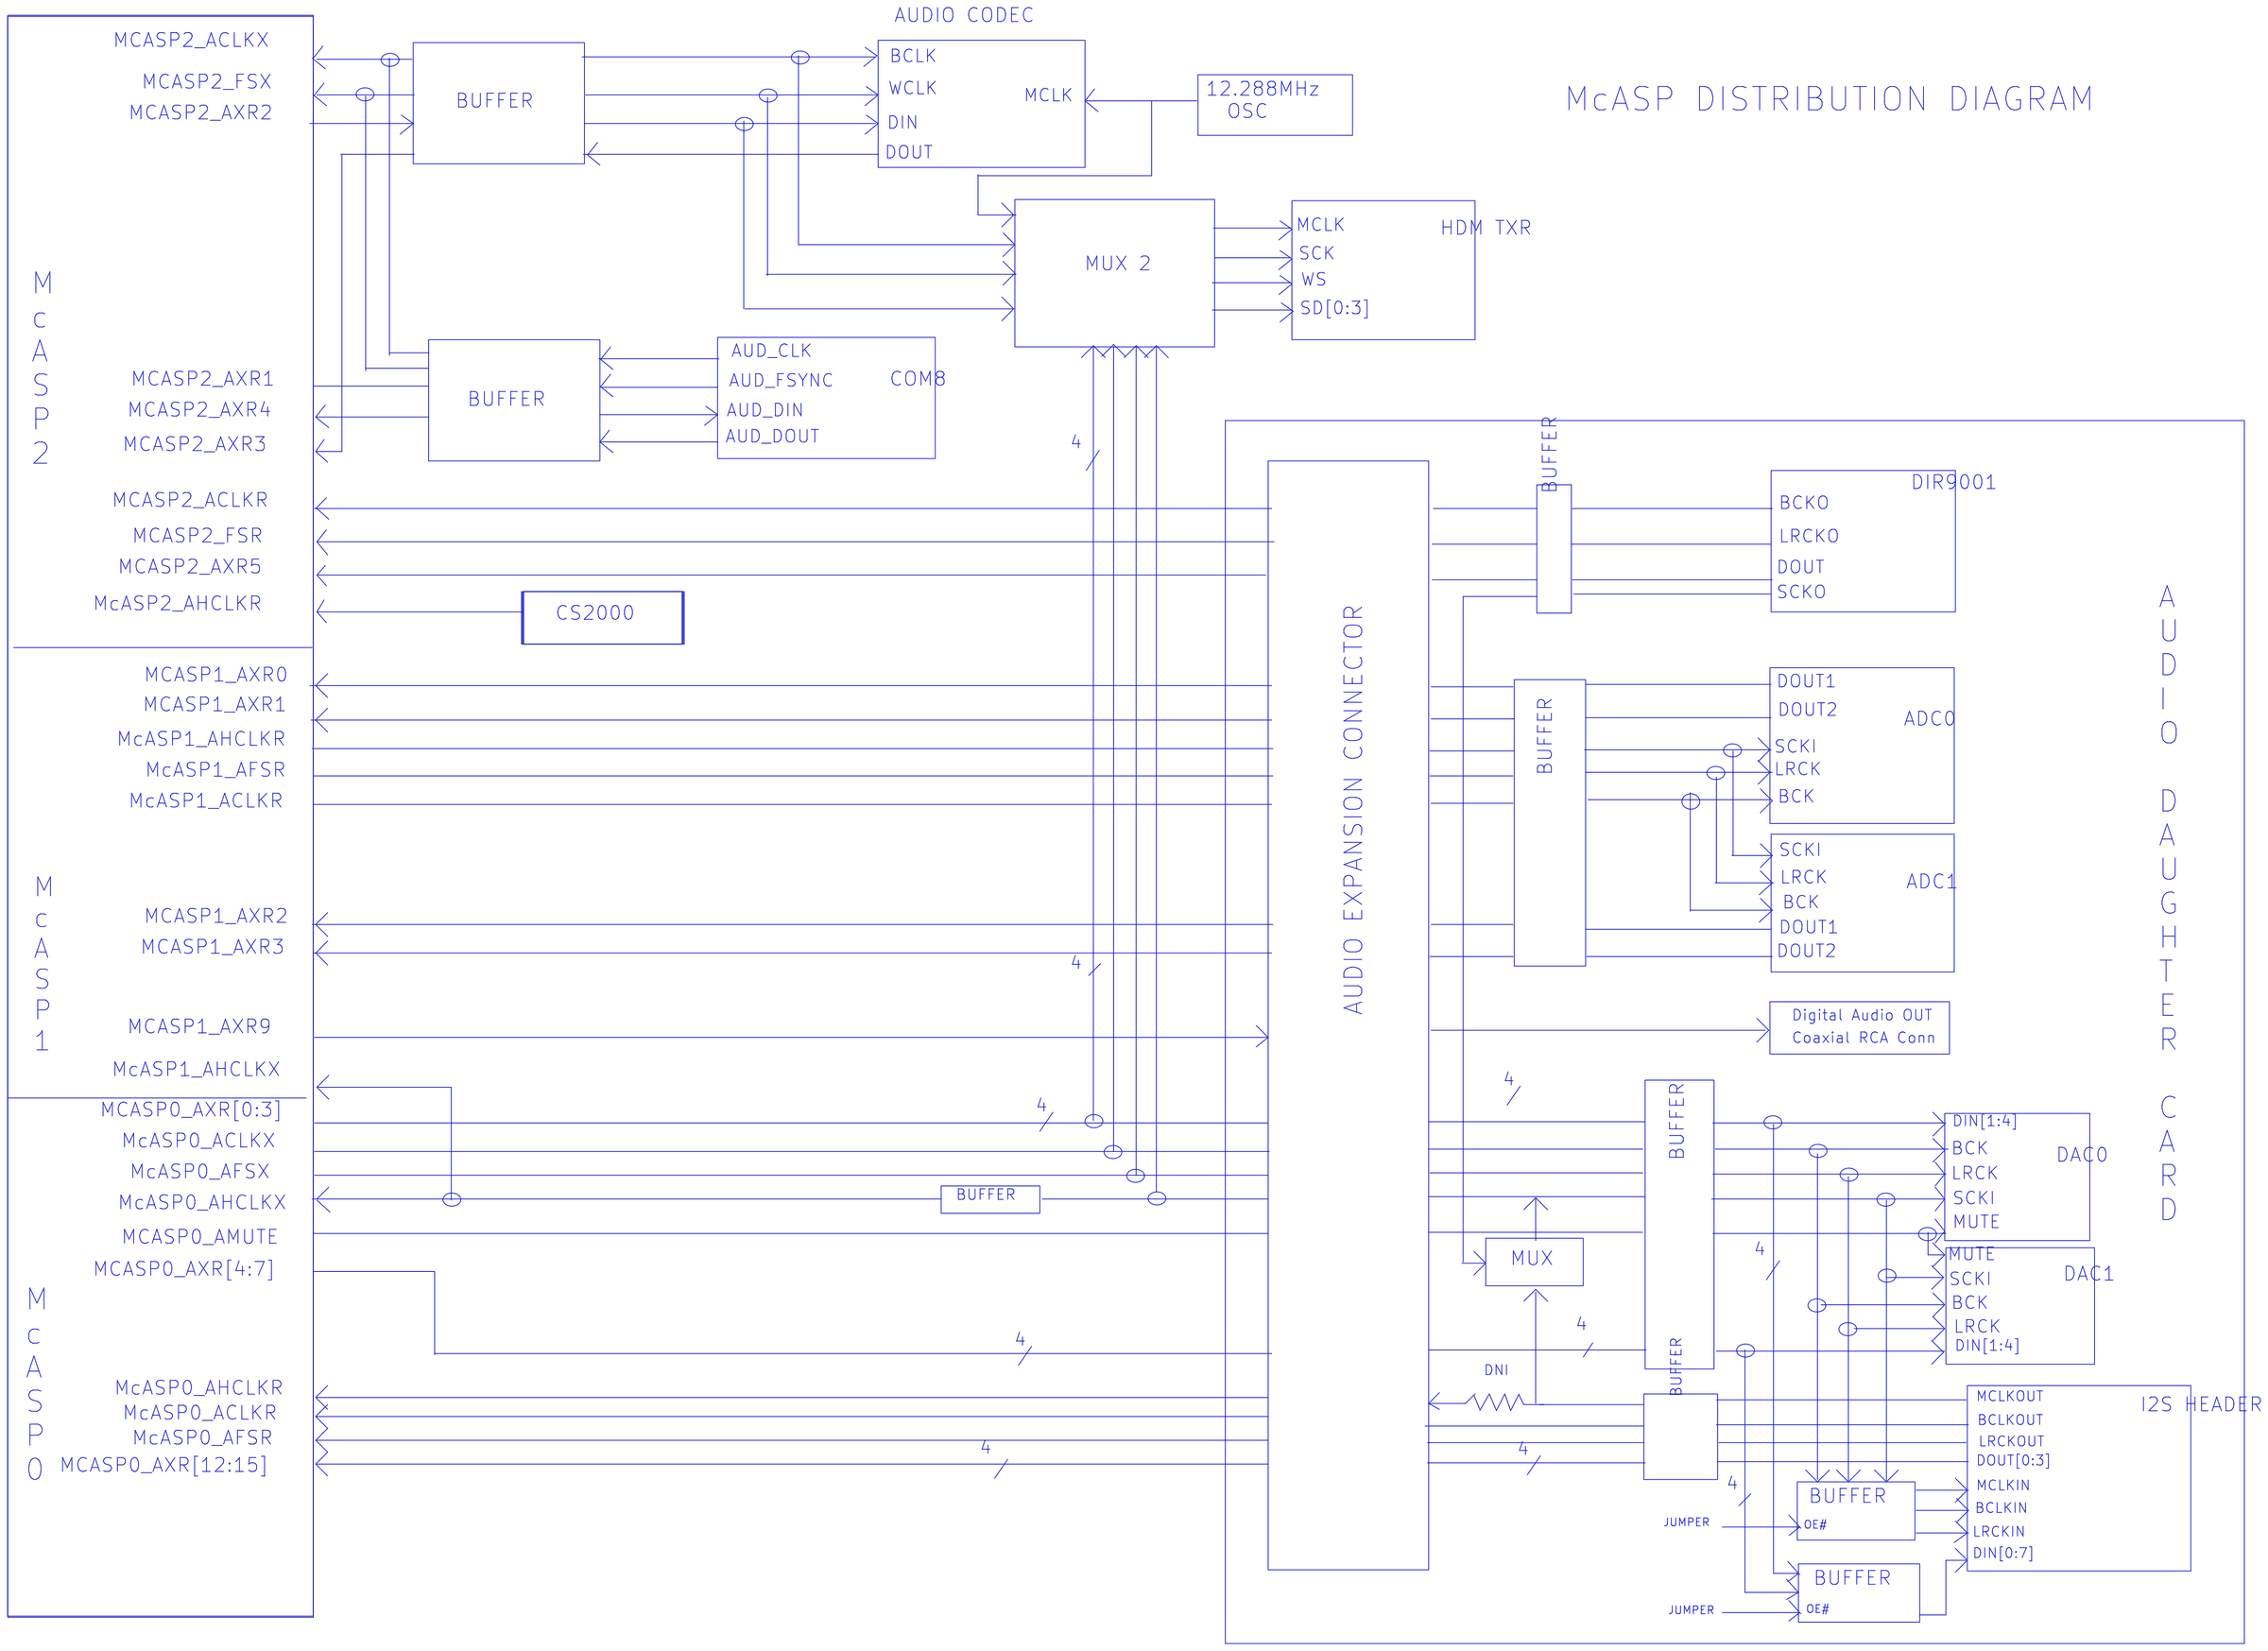
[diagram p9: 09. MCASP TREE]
11 10. SoC CLOCK & RESET: size C; title: SOC CLOCK & RESET
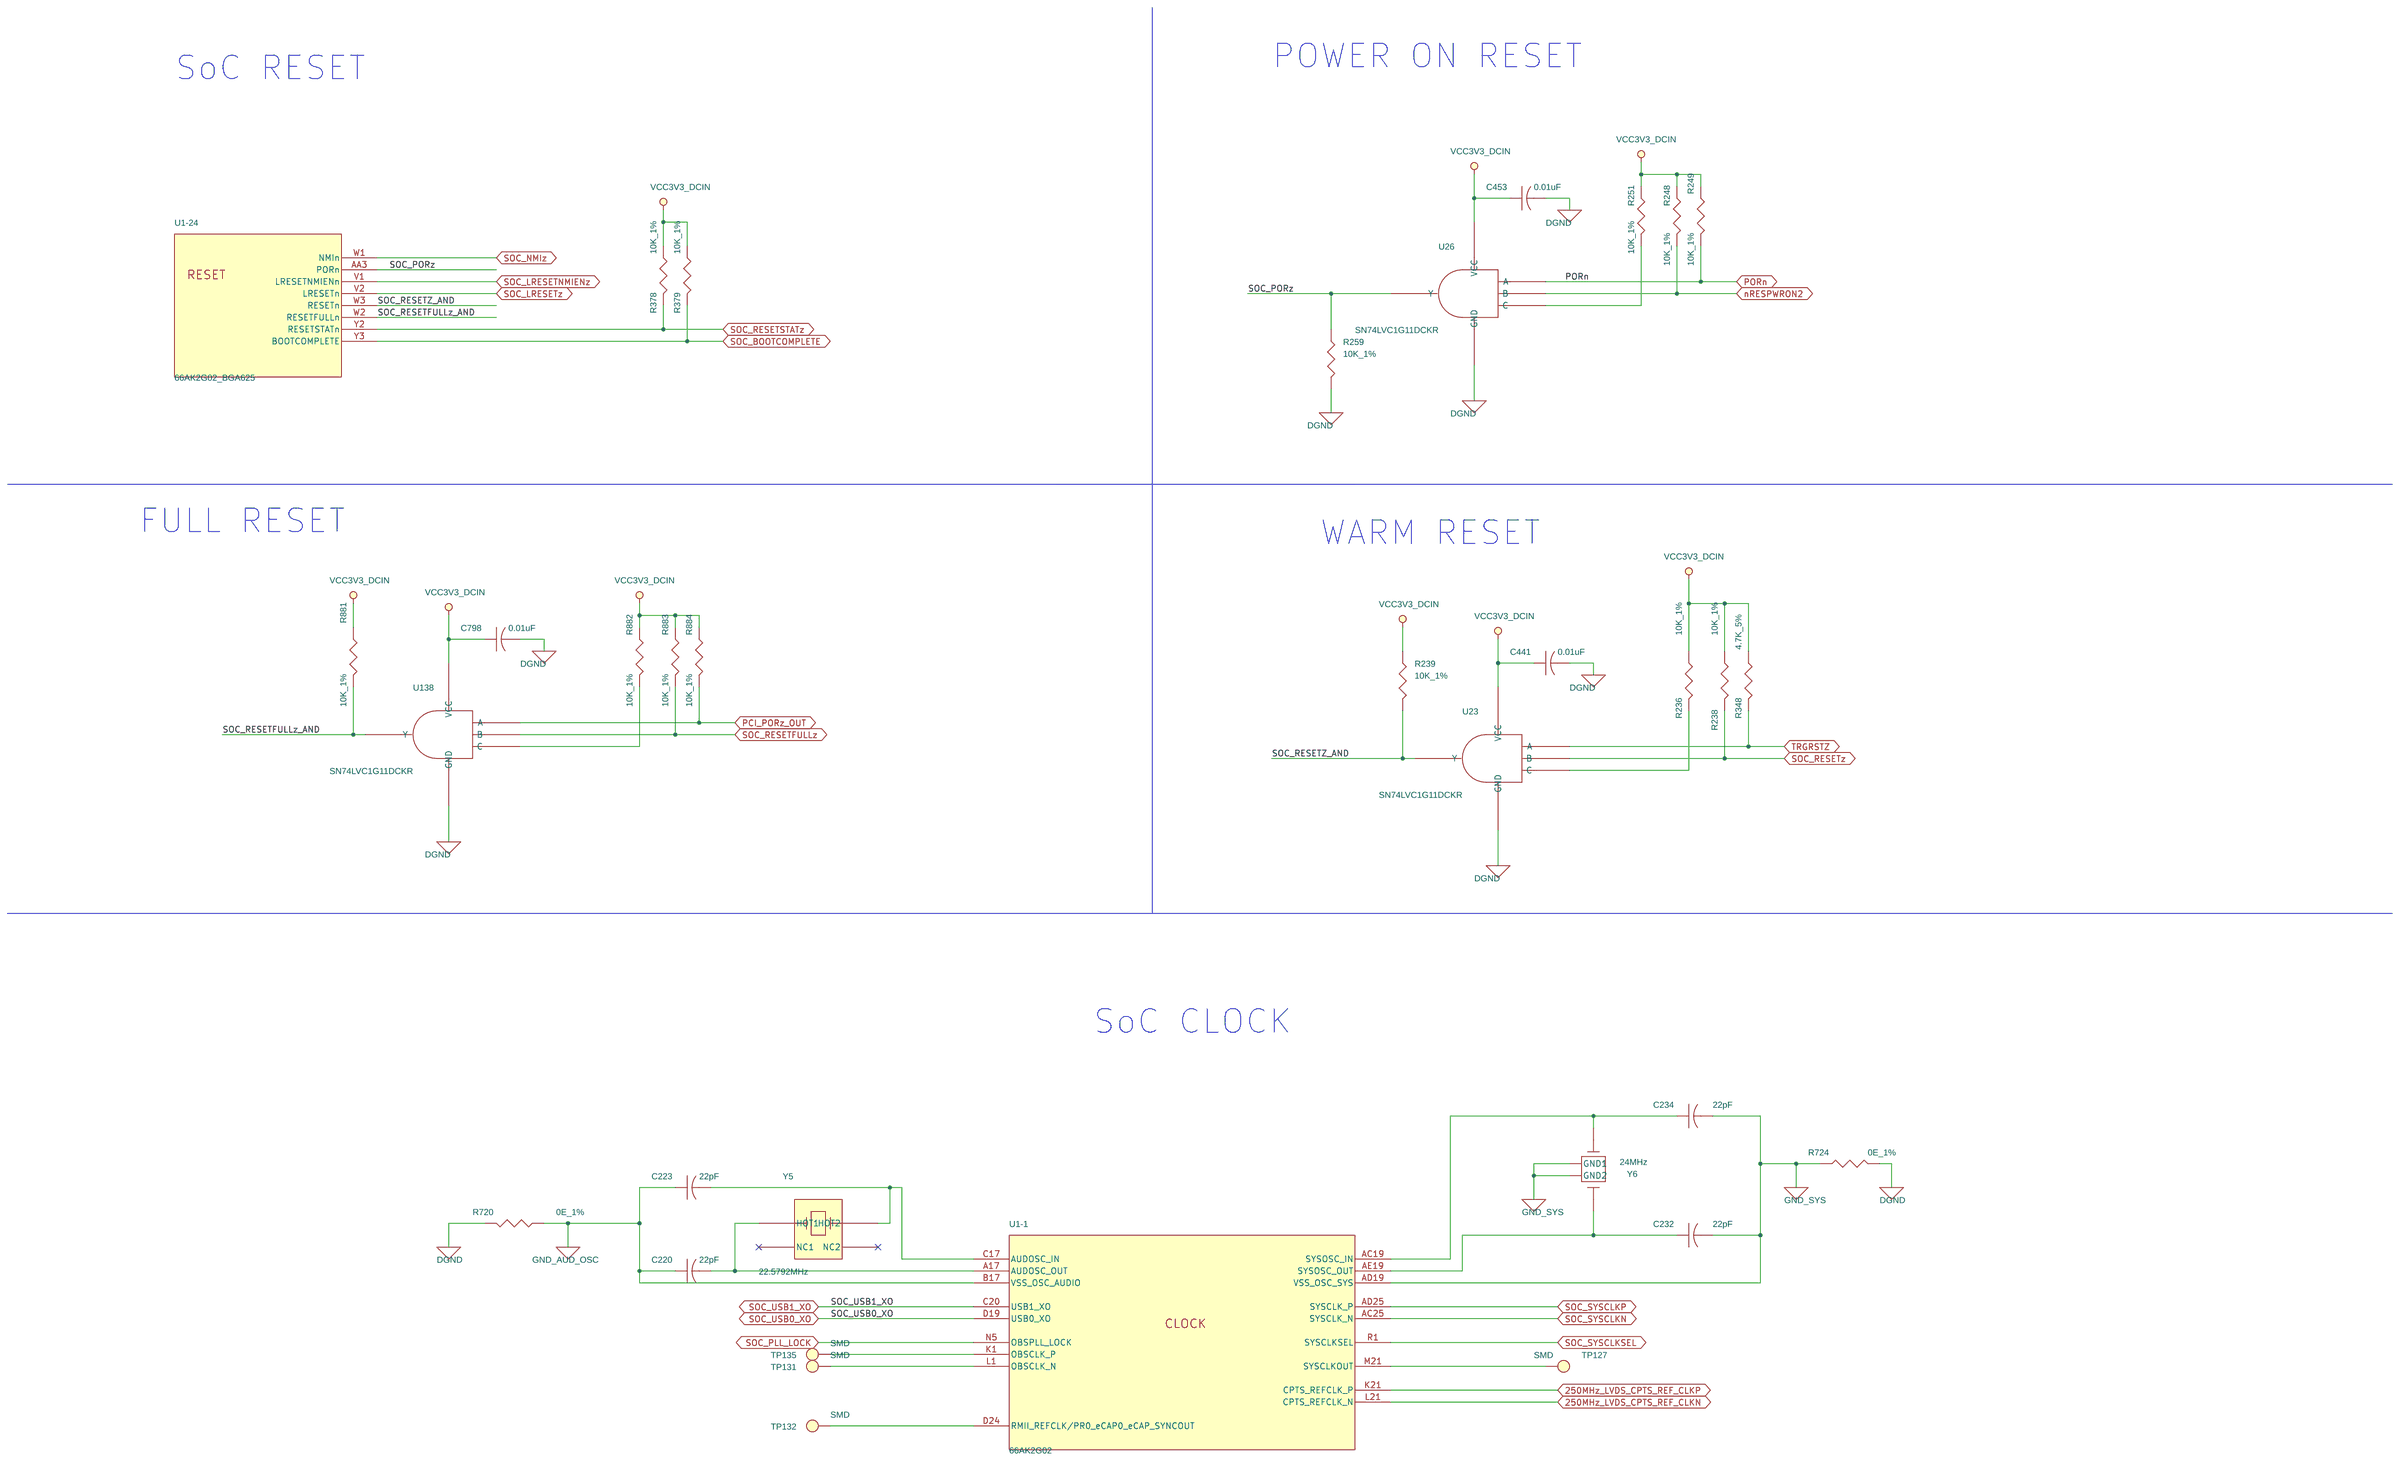
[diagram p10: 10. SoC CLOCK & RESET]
12 11. SoC GPIO,RESERVED PINS: size C; title: SOC GPIO, SMART REFLEX & TEST OUT
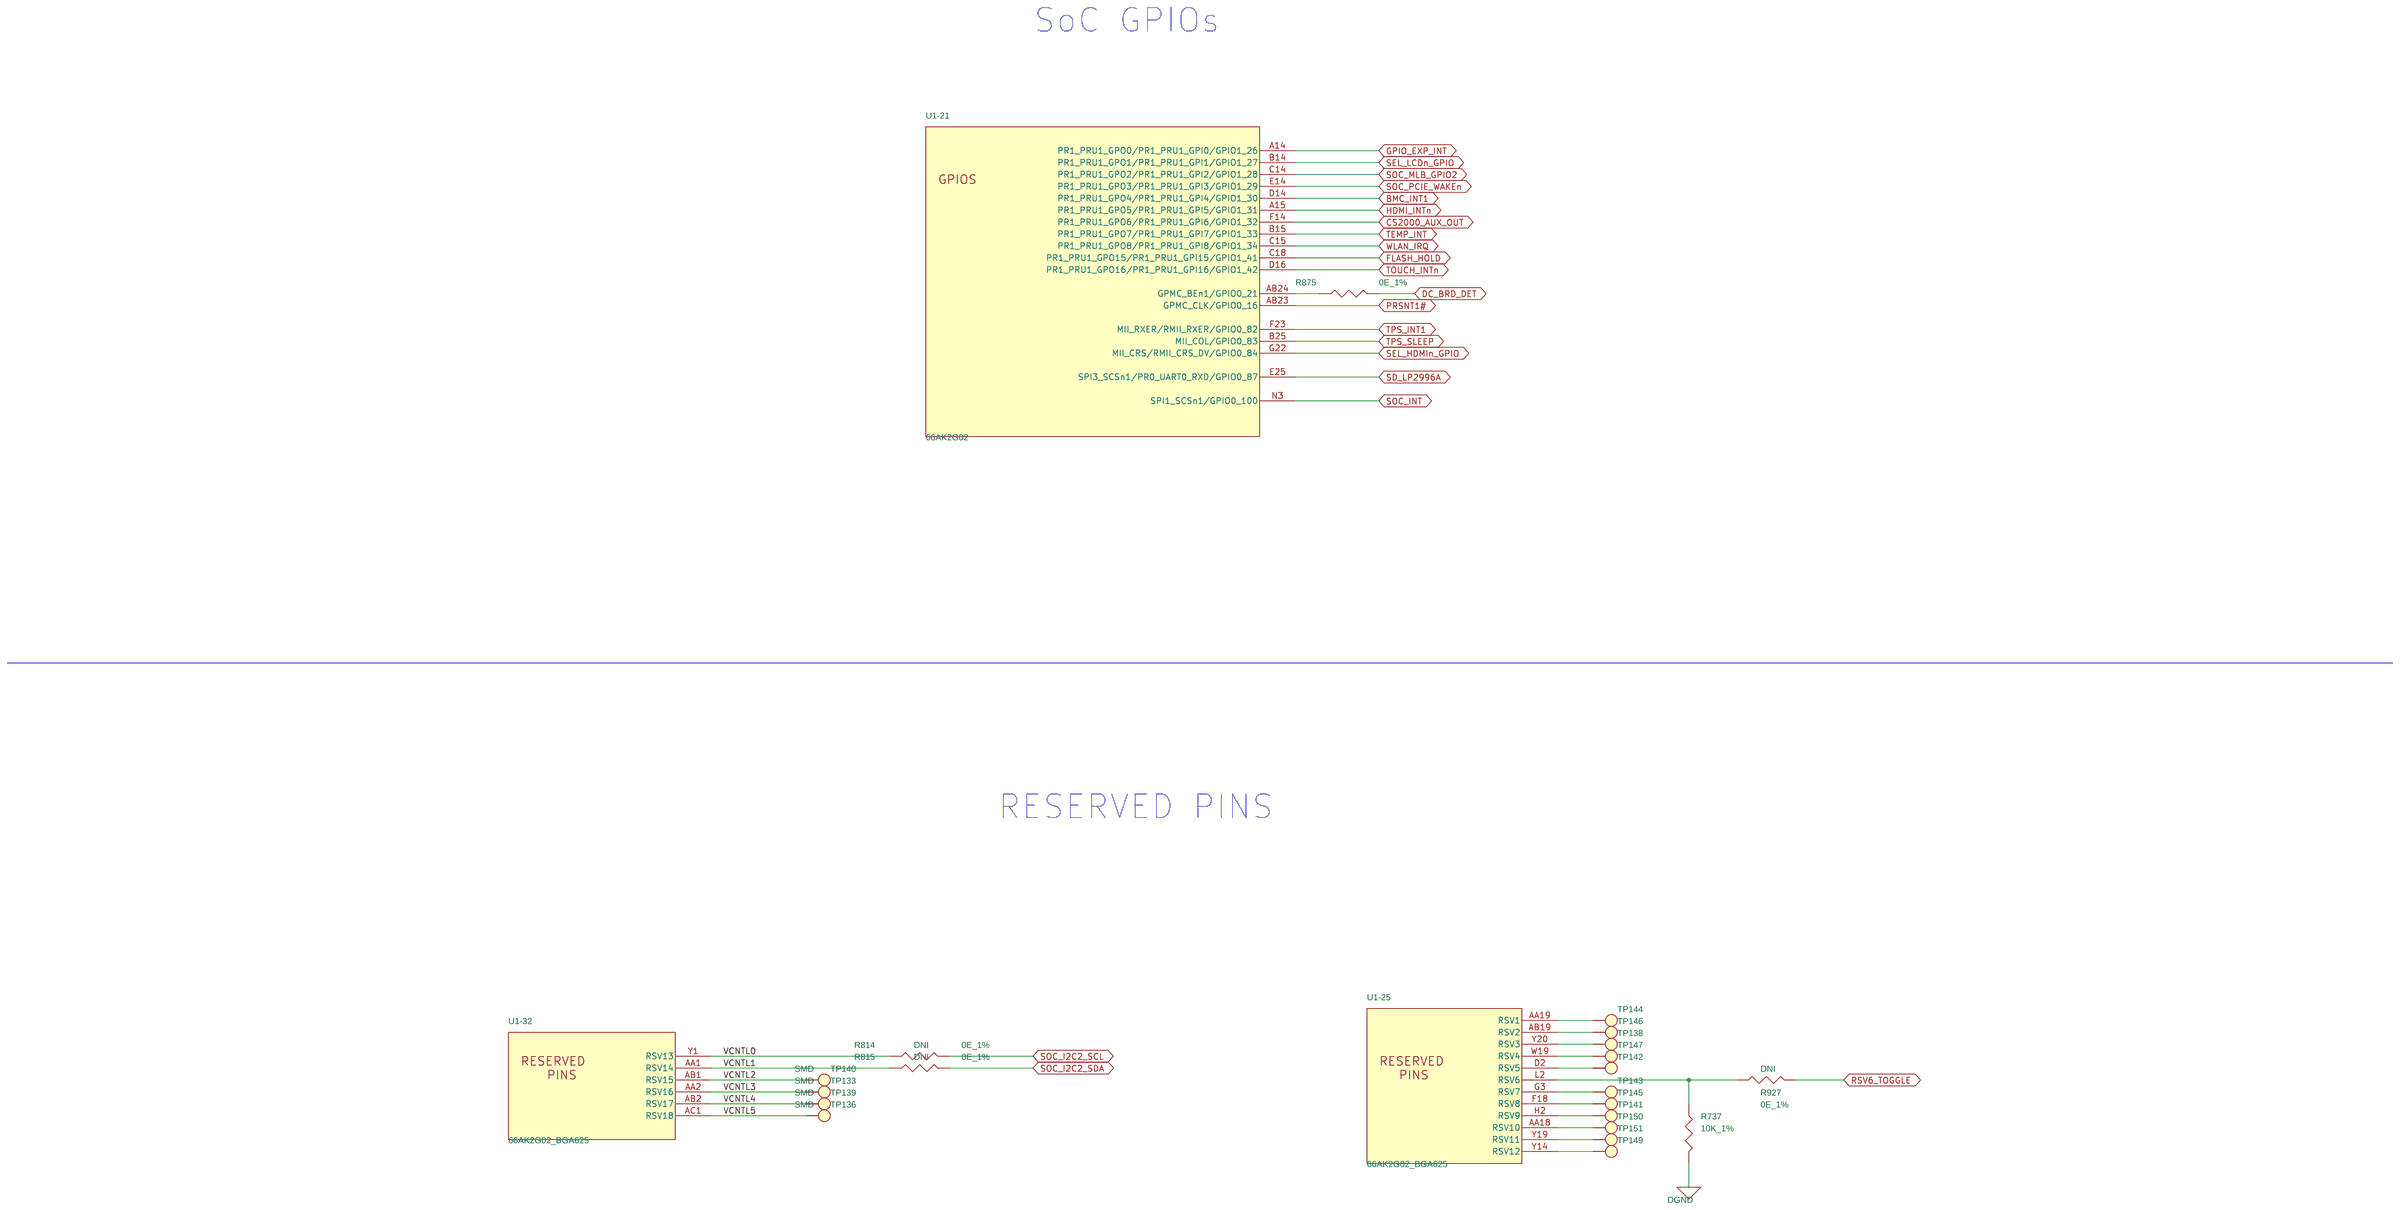
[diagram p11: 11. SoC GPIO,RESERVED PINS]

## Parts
sheet 10. SoC CLOCK & RESET
C220  22pF  [CAP0402]
C223  22pF  [CAP0402]
C232  22pF  [CAP0402]
C234  22pF  [CAP0402]
C441  0.01uF  [CAP0402]
C453  0.01uF  [CAP0402]
C798  0.01uF  [CAP0402]
R236  10K_1%  [RES0402]
R238  10K_1%  [RES0402]
R239  10K_1%  [RES0402]
R248  10K_1%  [RES0402]
R249  10K_1%  [RES0402]
R251  10K_1%  [RES0402]
R259  10K_1%  [RES0402]
R348  4.7K_5%  [RES0402]
R378  10K_1%  [RES0402]
R379  10K_1%  [RES0402]
R720  0E_1%  [RES0402]
R724  0E_1%  [RES0402]
R881  10K_1%  [RES0402]
R882  10K_1%  [RES0402]
R883  10K_1%  [RES0402]
R884  10K_1%  [RES0402]
TP127  SMD  [TP40_SMD]
TP131  SMD  [TP40_SMD]
TP132  SMD  [TP40_SMD]
TP135  SMD  [TP40_SMD]
U23  SN74LVC1G11DCKR  [SC70-6]
U26  SN74LVC1G11DCKR  [SC70-6]
U138  SN74LVC1G11DCKR  [SC70-6]
Y5  22.5792MHz  [XTAL4_NX3225GA_130X100_SMD]
Y6  24MHz  [XTAL4_ABM8G_130X105_SMD]
sheet 11. SoC GPIO,RESERVED PINS
R737  10K_1%  [RES0402]
R814  0E_1%  [RES0402]
R815  0E_1%  [RES0402]
R875  0E_1%  [RES0402]
R927  0E_1%  [RES0402]
TP133  SMD  [TP40_SMD]
TP136  SMD  [TP40_SMD]
TP138  SMD  [TP40_SMD]
TP139  SMD  [TP40_SMD]
TP140  SMD  [TP40_SMD]
TP141  SMD  [TP40_SMD]
TP142  SMD  [TP40_SMD]
TP143  SMD  [TP40_SMD]
TP144  SMD  [TP40_SMD]
TP145  SMD  [TP40_SMD]
TP146  SMD  [TP40_SMD]
TP147  SMD  [TP40_SMD]
TP149  SMD  [TP40_SMD]
TP150  SMD  [TP40_SMD]
TP151  SMD  [TP40_SMD]
sheet 36. CLOCK DISTRIBUTION 2
U1  66AK2G02_BGA625  [BGASKT625_31-49_1270x1270]  (sections -1,-10,-11,-12,-13,-14,-15,-16,-17,-18,-19,-2,-20,-21,-22,-23,-24,-25,-26,-27,-28,-29,-3,-30,-31,-32,-33,-34,-35,-36,-37,-38,-4,-5,-6,-7,-8,-9)
sheet 50. OVER VOLTAGE PROTECTION
C2  22uF  [CAP1210]
C23  100uF_35V  [CAPAE_D8CASE]
C824  0.1uF  [CAP0603]
C825  22uF_100V  [CAPAE_GCASE]
C826  0.1uF  [CAP0603]
C827  0.01uF  [CAP0402]
D3  B540C-13-F  [DIO_SMC]
D17  SMCJ64CA  [DIO_SMC]
D18  BZT52C13S  [DIO_SOD323]
D19  S1G-13-F  [DIO_SMA]
F2  5A  [FUSE_1206]
J3  CON_PWRJACK3_RAPC722  [CON_PWRJACK3_RAPC722_P_R_T]
J50  HDR_2X1  [HDR_2X1_100_S_T]
LD9  598-8170-107F  [LED_0805]
LD14  598-8110-107F  [LED_0805]
LD15  598-8110-107F  [LED_0805]
Q19  BSS138  [TO_SOT23-123]
Q20  SUM60N10-17-E3  [D2PAK-3]
R30  1K  [RES0402]
R892  0E  [RES0402]
R917  5.62k_1%  [RES0603]
R918  261K_1%  [RES0402]
R919  237K_1%  [RES0402]
R920  47K _1%  [RES0402]
R921  47K _1%  [RES0402]
R922  100K  [RES0402]
R923  10K  [RES1206]
R924  10K  [RES0402]
R925  100K  [RES0402]
R926  10K  [RES1206]
SW1  500ASSP3M2QE  [SW3_100_400X200_TH]
U149  LM5060MM  [MSOP10_19-68_120X120]

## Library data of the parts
C220 C223 C232 C234 = CAP: CAP CERAMIC 22pF 25V 5% NP0 0402; Chkd/date: SHREESHAIL/291105; Crtd /date: MAZHAR/040505; Custom_Duty: 15%; Customs_HS_Code: 85322990; Distributor_name: DIGIKEY; Distributor_part_number: 04023A220JAT2A-ND; Height: 0.60MM; Mfr_name: AVX CORPORATION; Mfr_part_number: 04023A220JAT2A; Mistral Part No: 120009030322-R; Package: 0402; Part_type: CAPACITORS\CERAMIC; Project: TELEMATICS-02; RoHS: RoHS; Tolerance: 5%; Voltage: 25V; Datasheet: Y:\MIS_DATABASE\DATASHEETS\CAPACITORS\AVX_MLC.PDF
C441 C453 C798 = CAP: CAP CERAMIC 0.01uF 16V 10% X7R 0402; Alternate_mfr_name_A: AVX CORPORATION; Alternate_mfr_name_B: KEMET; Alternate_mfr_name_D: TDK CORPORATION; Alternate_mfr_part_number_A: 0402YC103KAT2A; Alternate_mfr_part_number_B: C0402C103K4RACTU; Alternate_mfr_part_number_D: C1005X7R1C103K; Chkd/date: SHREESHAIL/180506; Crtd /date: MAZHAR/110506; Custom_Duty: 15%; Customs_HS_Code: 85322990; Distributor_name: DIGIKEY; Distributor_name_A: DIGIKEY; Distributor_name_B: DIGIKEY; Distributor_name_D: DIGIKEY; Distributor_part_number: PCC103BQCT-ND; Distributor_part_number_A: 478-1114-1-ND; Distributor_part_number_B: 399-1038-1-ND; Distributor_part_number_D: 445-1262-1-ND; Height: 0.55MM; Mfr_name: PANASONIC-ECG; Mfr_part_number: ECJ-0EB1C103K; Mistral Part No: 120009030032-R; Package: 0402; Part_type: CAPACITORS\CERAMIC; Project: VOCERA; RoHS: RoHS; Tolerance: 10%; Voltage: 16V; Datasheet: Y:\MIS_DATABASE\DATASHEETS\CAPACITORS\PAN-ECJ.PDF
R236 R238 R239 R248 R249 R251 R259 R378 R379 R737 R881-R884 R924 = RESISTOR: RES 10K 1/16W 1% 0402; Alternate_mfr_name_A: AVX CORPORATION; Alternate_mfr_name_B: PANASONIC-ECG-ECG; Alternate_mfr_name_C: YAGEO AMERICA; Alternate_mfr_name_D: VISHAY; Alternate_mfr_part_number_A: CR05-103F-H; Alternate_mfr_part_number_B: ERJ-2RKF1002X; Alternate_mfr_part_number_C: 9C04021A1002FLHF3; Alternate_mfr_part_number_D: CRCW040210K0FKED; Chkd/date: SHREESHAIL/310506; Crtd /date: GEETHA/290506; Custom_Duty: 15%; Customs_HS_Code: 85332119; Distributor_name: DIGIKEY; Distributor_name_A: NA; Distributor_name_B: DIGIKEY; Distributor_name_C: DIGIKEY; Distributor_name_D: DIGIKEY; Distributor_part_number: 311-10.0KLRTR-ND; Distributor_part_number_A: NA; Distributor_part_number_B: P10.0KLCT-ND; Distributor_part_number_C: 311-10.0KLCT-ND; Distributor_part_number_D: 541-10.0KLCT-ND; Height: 0.40MM; Mfr_name: YAGEO AMERICA; Mfr_part_number: RC0402FR-0710KL; Mistral Part No: 110009030220-P; Package: 0402; Part_type: RESISTORS\FIXED; Project: VOCERA; RoHS: Pb-Free; Tolerance: 1%; Wattage: 1/16W; Datasheet: Y:\MIS_DATABASE\DATASHEETS\RESISTORS\YAGEO-RC0402.PDF
R348 = RESISTOR: RES 4.7K 1/16W 5% 0402; Chkd/date: VASANTHA/190614; Crtd /date: NAVEED/160614; Custom_Duty: 15%; Customs_HS_Code: 85332119; Distributor_name: DIGIKEY; Distributor_part_number: RMCF0402JT4K70CT-ND; Height: 0.40MM; Mfr_name: STACKPOLE ELECTRONICS; Mfr_part_number: RMCF0402JT4K70; Mistral Part No: 110014060028-R; Package: 0402; Part_type: RESISTORS\FIXED; Project: AEGIS_POM; RoHS: RoHS; Temperature: -55°C+155°C; Tolerance: 5%; Voltage: NA; Wattage: 1/16W; Weight: NA; Datasheet: Y:\MIS_DATABASE\DATASHEETS\RESISTORS\RMCF-SERIES1.PDF
R720 R724 R875 = RESISTOR: RES 0E 1/16W 1% 0402; Chkd/date: MAZHAR/220709; Crtd /date: USMAN/270109; Custom_Duty: 15%; Customs_HS_Code: 85332119; Distributor_name: NA; Distributor_part_number: NA; Height: 0.40MM; Mfr_name: YAGEO AMERICA; Mfr_part_number: RC0402FR-070RL; Mistral Part No: 110009030085-P; Package: 0402; Part_type: RESISTORS\FIXED; Project: OMAP_EVM; RoHS: Pb-Free; Tolerance: 1%; Wattage: 1/16W; Datasheet: Y:\MIS_DATABASE\DATASHEETS\RESISTORS\CRCW0603.PDF
TP127 TP131-TP133 TP135 TP136 TP138-TP147 TP149-TP151 = TESTPOINT: TESTPOINT 40 SMD; Chkd/date: MAZHAR/190505; Crtd /date: MAZHAR/190505; Distributor_name: NA; Distributor_part_number: NA; Height: NA; Mfr_name: LOCAL; Mistral Part No: 130009030933; Part_type: MISC\TESTPOINT; Project: RAINIER-3
U23 U26 U138 = SN74LVC1G11DCKR_SC70-6: IC SINGLE 3-INPUT POSITIVE-AND GATE SC70-6; Chkd/date: SHREESHAIL/220506; Crtd /date: MAZHAR/150506; Custom_Duty: 15%; Customs_HS_Code: 85423100; Distributor_name: DIGIKEY; Distributor_part_number: 296-18066-1-ND; Height: 1.10MM; Mfr_name: TEXAS INSTRUMENTS; Mistral Part No: 141009030230-R; Part_type: ICS\DIGITAL\GATES; Project: VOCERA; RoHS: Sb/ Br FREE; Datasheet: Y:\MIS_DATABASE\DATASHEETS\ICS\DIGITAL\GATES\SN74LVC1G.PDF
Y5 = CRY_CX3225GB: CRY 22.5792MHz 18pF SMD; Chkd/date: VASANTHA/170714; Crtd /date: NAVEED/070714; Custom_Duty: 24%; Customs_HS_Code: 85439000; Distributor_name: DIGIKEY; Distributor_part_number: 1253-1195-1-ND; Height: 0.90MM; Mfr_name: KYOCERA; Mfr_part_number: CX3225GB22579P0HPQCC; Mistral Part No: 130014070003-R; Package: SMD; Part_type: CRYSTAL; Project: DCMIST_FPGA_CARD; RoHS: RoHS; Temperature: -40°C+85°C; Tolerance: NA; Voltage: NA; Wattage: NA; Weight: NA; Datasheet: Y:\MIS_DATABASE\DATASHEETS\MISC\CRY_OSC\CX3225GB.PDF
Y6 = CRY4_ABM8G: CRY 24MHZ 18pF SMD; Chkd/date: USMAN/251111; Crtd /date: CHAITHANYA/251111; Custom_Duty: 24%; Customs_HS_Code: 85439000; Distributor_name: DIGIKEY; Distributor_part_number: 535-10273-1-ND; Height: 1.00MM; Mfr_name: ABRACON; Mfr_part_number: ABM8G-24.000MHZ-18-D2Y-T; Mistral Part No: 130011110059-R; Package: SMD; Part_type: CRYSTAL; Project: NA10NG; RoHS: RoHS; Temperature: -40°C+85°C; Tolerance: NA; Voltage: NA; Wattage: NA; Weight: NA; Datasheet: Y:\MIS_DATABASE\DATASHEETS\MISC\CRY_OSC\ABM8G.PDF
R814 R815 R927 = RESISTOR: RES 0E 1/16W 1% 0402; Chkd/date: MAZHAR/220709; Crtd /date: USMAN/270109; Custom_Duty: 15%; Customs_HS_Code: 85332119; Distributor_name: NA; Distributor_part_number: NA; Height: 0.40MM; Loading: DNI; Mfr_name: YAGEO AMERICA; Mfr_part_number: RC0402FR-070RL; Mistral Part No: 110009030085-P; Package: 0402; Part_type: RESISTORS\FIXED; Project: OMAP_EVM; RoHS: Pb-Free; Tolerance: 1%; Wattage: 1/16W; Datasheet: Y:\MIS_DATABASE\DATASHEETS\RESISTORS\CRCW0603.PDF
U1 = 66AK2G02_BGA625: IC ARM CORTEX AND DSP 32 BIT MICROPROCESSOR BGA625; Chkd/date: NAVEED/141114; Color: Default; Crtd /date: VASANTHA/081014; Custom_Duty: 15%; Customs_HS_Code: 85423100; Distributor_name: NA; Distributor_part_number: NA; Height: 1.70MM; Location X-Coordinate: 0; Location Y-Coordinate: 0; Mfr_name: TEXAS INSTRUMENTS; Mfr_part_number: 66AK2G02; Mistral Part No: 141014100003; Package: BGA625; Part_type: ICS\DIGITAL\MICROPROCESSOR; Power Pins Visible: False; Primitive: DEFAULT; Project: GALILEO_EVM; Tolerance: NA; Voltage: NA; Wattage: NA; Weight: NA; Datasheet: Y:\MIS_DATABASE\DATASHEETS\ICS\DIGITAL\MICROCONTROLLER\SG-BGA-6094.PDF    Y:\MIS_DATABASE\DATASHEETS\ICS\DIGITAL\MICROCONTROLLER\SG-BGA_FP.PDF
C2 = CAP: CAP CERAMIC 22uF 25V 10% X7R 1210; Chkd/date: BAVISH/040311; Crtd /date: MAZHAR/190111; Custom_Duty: 15%; Customs_HS_Code: 85322990; Distributor_name: DIGIKEY; Distributor_part_number: 490-5313-1-ND; Height: 2.70MM; Mfr_name: MURATA; Mfr_part_number: GRM32ER71E226KE15L; Mistral Part No: 120011010016-R; Package: 1210; Part_type: CAPACITORS\CERAMIC; Project: ITS-PWR_CARD; RoHS: RoHS; Temperature: -55°C+125°C; Tolerance: 10%; Voltage: 25V; Wattage: NA; Weight: NA; Datasheet: Y:\MIS_DATABASE\DATASHEETS\CAPACITORS\GRM32,43,55.PDF
C23 = CAP_POL: CAP ELECTROLYTIC 100uF 35V 20% D8CASE_6666; Alternate_mfr_name_C: PANASONIC-ECG; Alternate_mfr_part_number_C: EEE-1VA101XP; Chkd/date: SHREESHAIL/020507; Crtd /date: MAZHAR/250407; Custom_Duty: 15%; Customs_HS_Code: 85322990; Distributor_name: DIGIKEY; Distributor_name_C: DIGIKEY; Distributor_part_number: PCE3836TR-ND; Distributor_part_number_C: PCE3951CT-ND; Height: 8.00MM; Mfr_name: PANASONIC-ECG; Mfr_part_number: EEE-FK1V101XP; Mistral Part No: 120009030526-R; Package: D8CASE_6666; Part_type: CAPACITORS\ELECTROLYTIC; Project: MICODER-1; RoHS: RoHS; Tolerance: 20%; Voltage: 35V; Datasheet: Y:\MIS_DATABASE\DATASHEETS\CAPACITORS\EEE-FK-SERIES.PDF
C824 C826 = CAP: CAP CERAMIC 0.1uF 100V 10% X7R 0603; Chkd/date: USMAN/280313; Crtd /date: USMAN/190313; Custom_Duty: 15%; Customs_HS_Code: 85322990; Distributor_name: DIGIKEY; Distributor_part_number: 311-1523-1-ND; Height: 0.90MM; Mfr_name: YAGEO AMERICA; Mfr_part_number: CC0603KRX7R0BB104; Mistral Part No: 120013030001-R; Package: 0603; Part_type: CAPACITORS\CERAMIC; Project: DTRM; RoHS: RoHS; Temperature: -55°C+125°C; Tolerance: 10%; Voltage: 100V; Wattage: NA; Weight: NA; Datasheet: Y:\MIS_DATABASE\DATASHEETS\CAPACITORS\YACC0603X.PDF
C825 = CAP_POL: CAP ELECTROLYTIC 22uF 100V 20% GCASE_103103; Chkd/date: USMAN/141211; Crtd /date: CHAITHANYA/131211; Custom_Duty: 15%; Customs_HS_Code: 85322990; Distributor_name: DIGIKEY; Distributor_part_number: PCE4250CT-ND; Height: 10.50MM; Mfr_name: PANASONIC-ECG; Mfr_part_number: EEE-HA2A220P; Mistral Part No: 120011120008-R; Package: GCASE_103103; Part_type: CAPACITORS\ELECTROLYTIC; Project: NA10NG; RoHS: RoHS; Temperature: -40°C+105°C; Tolerance: 20%; Voltage: 100V; Wattage: NA; Weight: NA; Datasheet: Y:\MIS_DATABASE\DATASHEETS\CAPACITORS\EEEHA-V-SERIES.PDF
C827 = CAP: CAP CERAMIC 0.01uF 16V 10% X7R 0402; Alternate_mfr_name_A: AVX CORPORATION; Alternate_mfr_name_B: KEMET; Alternate_mfr_name_D: TDK CORPORATION; Alternate_mfr_part_number_A: 0402YC103KAT2A; Alternate_mfr_part_number_B: C0402C103K4RACTU; Alternate_mfr_part_number_D: C1005X7R1C103K; Chkd/date: SHREESHAIL/180506; Crtd /date: MAZHAR/110506; Custom_Duty: 15%; Customs_HS_Code: 85322990; Distributor_name: DIGIKEY; Distributor_name_A: DIGIKEY; Distributor_name_B: DIGIKEY; Distributor_name_D: DIGIKEY; Distributor_part_number: PCC103BQCT-ND; Distributor_part_number_A: 478-1114-1-ND; Distributor_part_number_B: 399-1038-1-ND; Distributor_part_number_D: 445-1262-1-ND; Height: 0.55MM; Loading: DNI; Mfr_name: PANASONIC-ECG; Mfr_part_number: ECJ-0EB1C103K; Mistral Part No: 120009030032-R; Package: 0402; Part_type: CAPACITORS\CERAMIC; Project: VOCERA; RoHS: RoHS; Tolerance: 10%; Voltage: 16V; Datasheet: Y:\MIS_DATABASE\DATASHEETS\CAPACITORS\PAN-ECJ.PDF
D3 = DIODE_SCHOTTKY: DIODE SCHOTTKY 40V 5A SMC; Chkd/date: BAVISH/311210; Crtd /date: MAZHAR/201210; Custom_Duty: 15%; Customs_HS_Code: 85412900; Distributor_name: DIGIKEY; Distributor_part_number: B540C-FDICT-ND; Height: 2.5MM; Mfr_name: DIODES INC; Mistral Part No: 130010120033-R; Package: SMC; Part_type: DIODE\SCHOTTKY; Project: IEMS; RoHS: RoHS; Temperature: -55°C+125°C; Tolerance: NA; Voltage: 40V; Wattage: NA; Weight: 0.21g; Datasheet: Y:\MIS_DATABASE\DATASHEETS\DISCRETES\DIODES\B540C.PDF
D17 = DIODE_TVS_DUAL: DIODE TVS BI-DIE 1500W 64V SMC; Chkd/date: VASANTHA/101015; Crtd /date: VASANTHA/101015; Custom_Duty: 15%; Customs_HS_Code: 85412900; Distributor_name: DIGIKEY; Distributor_part_number: SMCJ64CALFCT-ND; Height: 2.62MM; Mfr_name: LITTLE FUSE; Mistral Part No: 130015100009-R; Package: SMC; Part_type: DIODE\TVS; Project: GALILEO_EVM; RoHS: RoHS; Temperature: -55°C+150°C; Tolerance: NA; Voltage: 64V; Wattage: NA; Weight: NA; Datasheet: Y:\MIS_DATABASE\DATASHEETS\DISCRETES\DIODES\LTFUSE-SMCJ.PDF
D18 = DIODE_ZENER: DIODE ZENER 13V 200mW SOD323; Chkd/date: MAZHAR/101210; Crtd /date: BAVISH/101210; Custom_Duty: 15%; Customs_HS_Code: 85412900; Distributor_name: DIGIKEY; Distributor_part_number: BZT52C13S-FDICT-ND; Height: 1.05MM; Mfr_name: DIODES INC; Mfr_part_number: BZT52C13S-7-F; Mistral Part No: 130010120013-R; Package: SOD323; Part_type: DIODE\ZENER; Project: IEMS; RoHS: RoHS; Temperature: -65°C+150°C; Tolerance: NA; Voltage: NA; Wattage: 200mW; Weight: 0.004g; Datasheet: Y:\MIS_DATABASE\DATASHEETS\DISCRETES\DIODES\BZT52C.PDF
D19 = DIODE: DIODE RECTIFIER 400V 1A SMA; Chkd/date: SUHAS/061010; Crtd /date: USMAN/220808; Custom_Duty: 15%; Customs_HS_Code: 85412900; Distributor_name: DIGIKEY; Distributor_part_number: S1G-FDICT-ND; Height: 2.30MM; Mfr_name: DIODES INC; Mistral Part No: 130009030153; Package: SMA; Part_type: DIODE\RECTIFIER; Project: CPB; Temperature: -65°C+150°C; Voltage: 400V; Weight: 0.0064g; Datasheet: Y:\MIS_DATABASE\DATASHEETS\DISCRETES\DIODES\S1.PDF
F2 = FUSE: FUSE 5A 32V 1206; Chkd/date: USMAN/200312; Crtd /date: CHAITHANYA/190312; Distributor_name: DIGIKEY; Distributor_part_number: F1608CT-ND; Height: 0.86MM; Mfr_name: LITTLE FUSE; Mfr_part_number: 0440005.WR; Mistral Part No: 130012030044-R; Package: 1206; Part_type: MISC\FUSE; Project: IP_CAMERA; RoHS: RoHS; Temperature: -55°C+150°C; Tolerance: NA; Voltage: 32V; Wattage: NA; Weight: NA; Datasheet: Y:\MIS_DATABASE\DATASHEETS\MISC\FUSE\0440_SERIES.PDF
J3 = CON_PWRJACK3_RAPC722: CON POWER JACK 3POS 5A 1.93MMPIN-DIA MALE RT TH; Chkd/date: MAZHAR/220311; Crtd /date: BAVISH/230211; Custom_Duty: 24%; Customs_HS_Code: 85369090; Distributor_name: DIGIKEY; Distributor_part_number: SC1313-ND; Height: 11.00MM; Mfr_name: SWITCHCRAFT; Mfr_part_number: RAPC722X; Mistral Part No: 150011020010-R; Package: THRU-HOLE; Part_type: CONNECTOR\JACK; Project: KENNEL; RoHS: RoHS; Temperature: NA; Tolerance: NA; Voltage: NA; Wattage: NA; Weight: SOIC8; Datasheet: Y:\MIS_DATABASE\DATASHEETS\CONNECTORS\RAPC722.PDF
J50 = HEADER_2X1: CON HDR 2X1 2.54MM PITCH ST TH; Alternate_mfr_name_A: SULLINS ELECTRONICS; Alternate_mfr_name_B: SAMTEC; Alternate_mfr_name_C: HANTRONIX; Alternate_mfr_part_number_A: PZC02SAAN; Alternate_mfr_part_number_B: TLW-102-06-G-S; Alternate_mfr_part_number_C: HDM20216L; Chkd/date: SHREESHAIL/140206; Crtd /date: MAZHAR/280405; Custom_Duty: 24%; Customs_HS_Code: 85369090; Distributor_name: DIGIKEY; Distributor_part_number: WM4000-ND; Height: 10.79MM; Mfr_name: MOLEX; Mfr_part_number: 22-03-2021; Mistral Part No: 150009030246-R; Package: THRU-HOLE; Part_type: CONNECTOR\HEADERS; Project: FPGA EXTENDER CARD; RoHS: RoHS; Datasheet: Y:\MIS_DATABASE\DATASHEETS\CONNECTORS\HEADER_X4030.PDF
LD9 = LED_598-8170-107F: LED ALINGAP GREEN CLEAR 0805 SMD; Chkd/date: BALACHANDAR/160514; Crtd /date: SARANYA/070514; Custom_Duty: 24%; Customs_HS_Code: 85437099; Distributor_name: DIGIKEY; Distributor_part_number: 350-2044-1-ND; Height: 0.70MM; Mfr_name: DIALIGHT; Mistral Part No: 130014050065-R; Package: 0805; Part_type: OPTO\LED; Project: AEGIS GP BETA2; RoHS: RoHS; Temperature: NA; Tolerance: NA; Voltage: NA; Wattage: NA; Weight: NA; Datasheet: Y:\MIS_DATABASE\DATASHEETS\DISCRETES\LEDS\598-SER.PDF
LD14 LD15 = LED_598-8170-107F: LED ALINGAP RED CLEAR 0805 SMD; Chkd/date: BALACHANDAR/160514; Crtd /date: SARANYA/070514; Custom_Duty: 24%; Customs_HS_Code: 85437099; Distributor_name: DIGIKEY; Distributor_part_number: 350-2038-1-ND; Height: 0.70MM; Mfr_name: DIALIGHT; Mistral Part No: 130014050069-R; Package: 0805; Part_type: OPTO\LED; Project: AEGIS GP BETA2; RoHS: RoHS; Temperature: NA; Tolerance: NA; Voltage: NA; Wattage: NA; Weight: NA; Datasheet: Y:\MIS_DATABASE\DATASHEETS\DISCRETES\LEDS\598-SER.PDF
Q19 = MOSFET_BSS138: IC MOSFET N-CHANNEL 50V 200mA SOT23-3; Chkd/date: SUHAS/191010; Crtd /date: USMAN/240709; Custom_Duty: 15%; Customs_HS_Code: 85423100; Distributor_name: DIGIKEY; Distributor_part_number: BSS138CT-ND; Height: 1.20MM; Mfr_name: DIODES INC; Mfr_part_number: BSS138-7-F; Mistral Part No: 142009070019-R; Package: SOT23-3; Part_type: ICS\POWER\MOSFET; Project: KHAN_MAIN; RoHS: RoHS; Temperature: -55°C+150°C; Voltage: 50V; Wattage: 300mW; Weight: 0.008g; Datasheet: Y:\MIS_DATABASE\DATASHEETS\DISCRETES\TRANSISTORS_FETS\BSS138.PDF
Q20 = MOSFET_IRFZ24NS: IC POWER MOSFET N-CHANNEL D2PAK; Chkd/date: VASANTHA/101015; Crtd /date: VASANTHA/101015; Custom_Duty: 15%; Customs_HS_Code: 85423100; Distributor_name: DIGIKEY; Distributor_part_number: SUM60N10-17-E3CT-ND; Height: 4.82MM; Mfr_name: VISHAY; Mistral Part No: 142015100008-R; Package: D2PAK; Part_type: ICS\POWER\MOSFET; Project: GALILEO_EVM; RoHS: RoHS; Temperature: -55°C+175°C; Tolerance: NA; Voltage: 100V; Wattage: NA; Weight: NA; Datasheet: Y:\MIS_DATABASE\DATASHEETS\DISCRETES\TRANSISTORS_FETS\SUM60N10.PDF
R30 = RESISTOR: RES 1K 1/16W 5% 0402; Alternate_mfr_name_A: AVX CORPORATION; Alternate_mfr_name_C: YAGEO AMERICA; Alternate_mfr_part_number_A: CR05-102J-H; Alternate_mfr_part_number_C: RC0402JR-071KL; Chkd/date: SHREESHAIL/121205; Crtd /date: MAZHAR/230805; Custom_Duty: 15%; Customs_HS_Code: 85332119; Distributor_name: DIGIKEY; Distributor_name_A: NA; Distributor_name_C: DIGIKEY; Distributor_part_number: P1.0KJCT-ND; Distributor_part_number_A: NA; Distributor_part_number_C: 311-1.0KJRCT-ND; Height: 0.40MM; Mfr_name: PANASONIC-ECG; Mfr_part_number: ERJ-2GEJ102X; Mistral Part No: 110009030400-R; Package: 0402; Part_type: RESISTORS\FIXED; Project: HSE; RoHS: RoHS; Tolerance: 5%; Wattage: 1/16W; Datasheet: Y:\MIS_DATABASE\DATASHEETS\RESISTORS\ERJ12.PDF
R892 = RESISTOR: RES 0E 1/10W 5% 0402; Chkd/date: NAVEED/241114; Crtd /date: NAVEED/201014; Custom_Duty: 15%; Customs_HS_Code: 85332119; Distributor_name: DIGIKEY; Distributor_part_number: P0.0JCT-ND; Height: 0.40MM; Mfr_name: PANASONIC-ECG; Mfr_part_number: ERJ-2GE0R00X; Mistral Part No: 110014100008-R; Package: 0402; Part_type: RESISTORS\FIXED; Project: AEGIS POM; RoHS: RoHS; Tolerance: 5%; Wattage: 1/10W; Datasheet: Y:\MIS_DATABASE\DATASHEETS\RESISTORS\ERJ12.PDF
R917 = RESISTOR: RES 5.62K 1/10W 1% 0603; Chkd/date: USMAN/141113; Crtd /date: USMAN/141113; Custom_Duty: 15%; Customs_HS_Code: 85332119; Distributor_name: DIGIKEY; Distributor_part_number: 541-5.62KHCT-ND; Height: 0.50MM; Mfr_name: VISHAY; Mfr_part_number: CRCW06035K62FKEA; Mistral Part No: 110013110005-R; Package: 0603; Part_type: RESISTORS\FIXED; Project: NPOL_FEP; RoHS: RoHS; Temperature: -55°C+155°C; Tolerance: 1%; Voltage: NA; Wattage: 1/10W; Weight: NA; Datasheet: Y:\MIS_DATABASE\DATASHEETS\RESISTORS\CRCW0603.PDF
R918 = RESISTOR: RES 261K 1/16W 1% 0402; Chkd/date: JEBRAN/250815; Crtd /date: JEBRAN/250815; Custom_Duty: 15%; Customs_HS_Code: 85332119; Distributor_name: DIGIKEY; Distributor_part_number: 311-261KLRCT-ND; Height: 0.40MM; Mfr_name: YAGEO AMERICA; Mfr_part_number: RC0402FR-07261KL; Mistral Part No: 110015080042-R; Package: 0402; Part_type: RESISTORS\FIXED; Project: OCTBTS3600; RoHS: RoHS; Temperature: -55°C+155°C; Tolerance: 1%; Voltage: NA; Wattage: 1/16W; Weight: NA; Datasheet: Y:\MIS_DATABASE\DATASHEETS\RESISTORS\YAGEO.PDF
R919 = RESISTOR: RES 237K 1/16W 1% 0402; Chkd/date: JEBRAN/250815; Crtd /date: JEBRAN/250815; Distributor_name: DIGIKEY; Distributor_part_number: RMCF0402FT237KCT-ND; Height: 0.40MM; Mfr_name: STACKPOLE ELECTRONICS; Mfr_part_number: RMCF0402FT237K; Mistral Part No: 110015080038-R; Package: 0402; Part_type: RESISTORS\FIXED; Project: OCTBTS3600; Temperature: -55°C+155°C; Tolerance: 1%; Voltage: NA; Wattage: 1/16W; Weight: NA; Datasheet: Y:\MIS_DATABASE\DATASHEETS\RESISTORS\RMCF-SERIES1.PDF
R920 R921 = RESISTOR: RES 47K 1/16W 1% 0402; Alternate_mfr_name_D: ROHM; Alternate_mfr_part_number_D: MCR01MZPF4702; Chkd/date: SHREESHAIL/24050; Crtd /date: MAZHAR/141206; Custom_Duty: 15%; Customs_HS_Code: 85332119; Distributor_name: DIGIKEY; Distributor_name_D: DIGIKEY; Distributor_part_number: 311-47.0KLRCT-ND; Distributor_part_number_D: RHM47.0KLCT-ND; Height: 0.40MM; Mfr_name: YAGEO AMERICA; Mfr_part_number: RC0402FR-0747KL; Mistral Part No: 110009030884-P; Package: 0402; Part_type: RESISTORS\FIXED; Project: ADR1B; RoHS: Pb-Free; Tolerance: 1%; Wattage: 1/16W; Datasheet: Y:\MIS_DATABASE\DATASHEETS\RESISTORS\YAGEO-RC0402.PDF
R922 R925 = RESISTOR: RES 100K 1/16W 5% 0402; Alternate_mfr_name_A: AVX CORPORATION; Alternate_mfr_part_number_A: CR05-104J-H; Chkd/date: SHREESHAIL/200406; Crtd /date: GEETHA/190406; Custom_Duty: 15%; Customs_HS_Code: 85332119; Distributor_name: DIGIKEY; Distributor_name_A: NA; Distributor_part_number: P100KJCT-ND; Distributor_part_number_A: NA; Height: 0.40MM; Mfr_name: PANASONIC-ECG; Mfr_part_number: ERJ-2GEJ104X; Mistral Part No: 110009030177-R; Package: 0402; Part_type: RESISTORS\FIXED; Project: RED EYE; RoHS: RoHS; Tolerance: 5%; Wattage: 1/16W; Datasheet: Y:\MIS_DATABASE\DATASHEETS\RESISTORS\ERJ12.PDF
R923 R926 = RESISTOR: RES 10K 2/3W 5% 1206; Chkd/date: VASANTHA/101015; Crtd /date: VASANTHA/101015; Custom_Duty: 15%; Customs_HS_Code: 85332119; Distributor_name: DIGIKEY; Distributor_part_number: P10KALCT-ND; Height: 0.70MM; Mfr_name: PANASONIC; Mfr_part_number: ERJ-P08J103V; Mistral Part No: 110015090016-R; Package: 1206; Part_type: RESISTORS\FIXED; Project: GALILEO_EVM; RoHS: RoHS; Temperature: -55°C+155°C; Tolerance: 5%; Voltage: NA; Wattage: 2/3W; Weight: 10g/1000pcs; Datasheet: Y:\MIS_DATABASE\DATASHEETS\RESISTORS\ERJ_SERIES.PDF
SW1 = SW3_SPST_500A: SWITCH SLIDE SPST TH; Alternate_mfr_name_A: C&K COMPONENTS; Alternate_mfr_part_number_A: TS03CBE; Chkd/date: SUHAS/121010; Crtd /date: USMAN/050509; Custom_Duty: 24%; Customs_HS_Code: 85369090; Distributor_name: DIGIKEY; Distributor_part_number: 500ASSP3M2QE-ND; Height: 12.91MM; Mfr_name: E-SWITCH; Mistral Part No: 130009060024; Package: THRU-HOLE; Part_type: ELECTRO-MECHANICAL\SWITCH; Project: STORM2; Temperature: -30°C+85°C; Datasheet: Y:\MIS_DATABASE\DATASHEETS\MISC\SWITCHES\500ASSP3.PDF
U149 = LM5060_MSOP10: IC CONTROLLER HIGH-SIDE PROTECTION VSSOP10; Chkd/date: VASANTHA/101015; Crtd /date: VASANTHA/101015; Custom_Duty: 15%; Customs_HS_Code: 85423100; Distributor_name: DIGIKEY; Distributor_part_number: 296-39024-1-ND; Height: 1.10MM; Mfr_name: TEXAS INSTRUMENTS; Mfr_part_number: LM5060MM/NOPB; Mistral Part No: 142015100007-R; Package: VSSOP10; Part_type: ICS\POWER\MANAGEMENT; Project: GALILEO_EVM; RoHS: RoHS; Temperature: -40°C+125°C; Tolerance: NA; Voltage: NA; Wattage: NA; Weight: NA; Datasheet: Y:\MIS_DATABASE\DATASHEETS\ICS\POWER\LM5060-TI.PDF

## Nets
DGND: C2.2 C23.2 C441.2 C453.2 C798.2 C824.2 C825.2 C826.2 C827.2 D17.2(ANODE) D18.2(ANODE) D19.2(A) J3.2 J3.3 LD9.1 Q19.2(S) R259.1 R720.2 R724.2 R737.1 R920.2 R921.2 U23.2(GND) U26.2(GND) U138.2(GND) U149.6(GND) ; also on sheet 13 14 15 16 17 18 19 20 21 22 23 24 25 26 27 28 29 30 31 32 33 34 35 36 37 38 39 40 41 42 43 44 45 46 47 48 49 50
GND_AUD_OSC: C220.1 C223.1 R720.1 U1.B17(VSS_OSC_AUDIO)
GND_SYS: C232.2 C234.2 R724.1 U1.AD19(VSS_OSC_SYS) Y6.2(GND1) Y6.4(GND2)
VCC3V3_DCIN: C441.1 C453.1 C798.1 R236.2 R238.2 R239.2 R248.2 R249.2 R251.2 R348.1 R378.1 R379.1 R881.2 R882.2 R883.2 R884.2 U23.5(VCC) U26.5(VCC) U138.5(VCC) ; also on sheet 17 18 19 20 21 22 23 24 25 26 27 28 29 30 31 32 33 34 35 36 37 38 43 44 45 46 47 48 50
VCC12V0_DC_IN: C2.1 C23.1 J50.1 Q20.3(S) R30.1 R892.1 ; also on sheet 26 31 33 34 47 48 50
VINPUT: C824.1 C825.1 D3.1(CATHODE) J50.2 Q20.4(D) R917.1 R918.1 R919.1 R922.1 R923.1 R925.2 U149.2(VIN)
250MHz_LVDS_CPTS_REF_CLKN: U1.L21(CPTS_REFCLK_N) ; also on sheet 36
250MHz_LVDS_CPTS_REF_CLKP: U1.K21(CPTS_REFCLK_P) ; also on sheet 36
BMC_INT1: U1.D14(PR1_PRU1_GPO4/PR1_PRU1_GPI4/GPIO1_30) ; also on sheet 47
CS2000_AUX_OUT: U1.F14(PR1_PRU1_GPO6/PR1_PRU1_GPI6/GPIO1_32) ; also on sheet 37
DC_BRD_DET: R875.2 ; also on sheet 22 33 45
FLASH_HOLD: U1.C18(PR1_PRU1_GPO15/PR1_PRU1_GPI15/GPIO1_41) ; also on sheet 17
GATE: C827.1 Q20.1(G) U149.10(GATE)
GPIO_EXP_INT: U1.A14(PR1_PRU1_GPO0/PR1_PRU1_GPI0/GPIO1_26) ; also on sheet 35
HDMI_INTn: U1.A15(PR1_PRU1_GPO5/PR1_PRU1_GPI5/GPIO1_31) ; also on sheet 22
nRESPWRON2: R248.1 U26.3(B) ; also on sheet 45 49
PCI_PORz_OUT: R884.1 U138.1(A) ; also on sheet 26
PGD: R924.1 R925.1 U149.8(NPGD)
PORn: R249.1 U26.1(A) ; also on sheet 47
PRSNT1#: U1.AB23(GPMC_CLK/GPIO0_16) ; also on sheet 26
RSV6_TOGGLE: R927.2 ; also on sheet 47
SD_LP2996A: U1.E25(SPI3_SCSn1/PR0_UART0_RXD/GPIO0_87) ; also on sheet 50
SEL_HDMIn_GPIO: U1.G22(MII_CRS/RMII_CRS_DV/GPIO0_84) ; also on sheet 20
SEL_LCDn_GPIO: U1.B14(PR1_PRU1_GPO1/PR1_PRU1_GPI1/GPIO1_27) ; also on sheet 20
SOC_BOOTCOMPLETE: R379.2 U1.Y3(BOOTCOMPLETE) ; also on sheet 45
SOC_I2C2_SCL: R814.2 ; also on sheet 35 49
SOC_I2C2_SDA: R815.2 ; also on sheet 35 49
SOC_INT: U1.N3(SPI1_SCSn1/GPIO0_100) ; also on sheet 47
SOC_LRESETNMIENz: U1.V1(LRESETNMIENn) ; also on sheet 47
SOC_LRESETz: U1.V2(LRESETn) ; also on sheet 47
SOC_MLB_GPIO2: U1.C14(PR1_PRU1_GPO2/PR1_PRU1_GPI2/GPIO1_28) ; also on sheet 31
SOC_NMIz: U1.W1(NMIn) ; also on sheet 47
SOC_PCIE_WAKEn: U1.E14(PR1_PRU1_GPO3/PR1_PRU1_GPI3/GPIO1_29) ; also on sheet 26
SOC_PLL_LOCK: U1.N5(OBSPLL_LOCK) ; also on sheet 45 46
SOC_PORz: R259.2 U1.AA3(PORn) U26.4(Y)
SOC_RESETFULLz: R883.1 U138.3(B) ; also on sheet 47
SOC_RESETFULLz_AND: R881.1 U1.W2(RESETFULLn) U138.4(Y)
SOC_RESETSTATz: R378.2 U1.Y2(RESETSTATn) ; also on sheet 17 18 21 22 23 25 26 31 33 45 46
SOC_RESETz: R238.1 U23.3(B) ; also on sheet 47
SOC_RESETZ_AND: R239.1 U1.W3(RESETn) U23.4(Y)
SOC_SYSCLKN: U1.AC25(SYSCLK_N) ; also on sheet 36
SOC_SYSCLKP: U1.AD25(SYSCLK_P) ; also on sheet 36
SOC_SYSCLKSEL: U1.R1(SYSCLKSEL) ; also on sheet 47
SOC_USB0_XO: U1.D19(USB0_XO) ; also on sheet 36
SOC_USB1_XO: U1.C20(USB1_XO) ; also on sheet 36
TEMP_INT: U1.B15(PR1_PRU1_GPO7/PR1_PRU1_GPI7/GPIO1_33) ; also on sheet 35
TOUCH_INTn: U1.D16(PR1_PRU1_GPO16/PR1_PRU1_GPI16/GPIO1_42) ; also on sheet 21
TPS_INT1: U1.F23(MII_RXER/RMII_RXER/GPIO0_82) ; also on sheet 49
TPS_SLEEP: U1.B25(MII_COL/GPIO0_83) ; also on sheet 49
TRGRSTZ: R348.2 U23.1(A) ; also on sheet 43 45
VCNTL0: R814.1 U1.Y1(RSV13)
VCNTL1: R815.1 U1.AA1(RSV14)
VCNTL2: TP140.1(TP) U1.AB1(RSV15)
VCNTL3: TP133.1(TP) U1.AA2(RSV16)
VCNTL4: TP139.1(TP) U1.AB2(RSV17)
VCNTL5: TP136.1(TP) U1.AC1(RSV18)
WLAN_IRQ: U1.C15(PR1_PRU1_GPO8/PR1_PRU1_GPI8/GPIO1_34) ; also on sheet 30
N17124284: C234.1 U1.AC19(SYSOSC_IN) Y6.1
N17124300: C232.1 U1.AE19(SYSOSC_OUT) Y6.3
N19207451: TP127.1(TP) U1.M21(SYSCLKOUT)
N19207912: C223.2 U1.C17(AUDOSC_IN) Y5.3(HOT2)
N19207996: C220.2 U1.A17(AUDOSC_OUT) Y5.1(HOT1)
N19208525: TP135.1(TP) U1.K1(OBSCLK_P)
N19208527: TP131.1(TP) U1.L1(OBSCLK_N)
N19208590: TP132.1(TP) U1.D24(RMII_REFCLK/PR0_eCAP0_eCAP_SYNCOUT)
N19364584: TP138.1(TP) U1.Y20(RSV3)
N19364586: TP146.1(TP) U1.AB19(RSV2)
N19364588: TP144.1(TP) U1.AA19(RSV1)
N19364600: TP147.1(TP) U1.W19(RSV4)
N19626375: R251.1 U26.6(C)
N20165134: R236.1 U23.6(C)
N24555288: R875.1 U1.AB24(GPMC_BEn1/GPIO0_21)
N25715331: R882.1 U138.6(C)
N27876508: D3.2(ANODE) D17.1(CATHODE) F2.2 R926.2
N28004667: R917.2 U149.1(SENSE)
N28004936: R892.2 U149.9(OUT)
N28004974: C826.1 U149.7(TIMER)
N28005348: LD9.2 R30.2
N28027381: LD14.1 Q19.3(D)
N28029912: R922.2 U149.5(EN)
N28030740: LD14.2 R923.2
N28032220: R919.2 R921.1 U149.4(UVLO)
N28032223: R918.2 R920.1 U149.3(OVP)
N28034077: J3.1 SW1.3
N28055806: F2.1 SW1.2
N28098623: D18.1(CATHODE) Q19.1(G) R924.2
N28173616: D19.1(K) LD15.2
N28350475: LD15.1 R926.1
N28489979: R737.2 R927.1 U1.L2(RSV6)
N28490065: TP143.1(TP) U1.G3(RSV7)
N28490068: TP149.1(TP) U1.Y14(RSV12)
N28490071: TP151.1(TP) U1.Y19(RSV11)
N28490074: TP145.1(TP) U1.F18(RSV8)
N28490077: TP141.1(TP) U1.H2(RSV9)
N28490080: TP150.1(TP) U1.AA18(RSV10)
N28490154: TP142.1(TP) U1.D2(RSV5)

Not connected (* = marked no-connect by the designer): SW1 1*; Y5 2(NC1)* 4(NC2)*

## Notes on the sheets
sheet 1
- OVER VOLTAGE PROTECTION CIRCUIT
- RED
- Note:-
- Vinput nominal = 12V
  I input max    = 5A
- Condition
- LED Status(LD15)
- Reverse Voltage
- ON
- Fault Indication
- RED
- Condition
- LED Status(LD14)
- VINPUT between 11 to 13V
           &
    Current below 5A
- OFF
- VINPUT above 13V or below 11V
                &
        Current above 5A
- ON
- Note:-
- When fault is indicated ,set to proper voltage and power cycle the board.
sheet 2
- K2GEVM
- TABLE OF CONTENTS
- CONTENTS
- CONTENTS
- PAGE
- PAGE
- REV
- D
- 01
- TABLE OF CONTENTS
- 37
- EMU & MIPI60 CONNECTOR
- VER
- 1.5
- 02
- REVISION HISTORY
- 38
- JTAG_XDS200_1
- 03
- BLOCK DIAGRAM - K2G EVM
- 39
- JTAG_XDS200_2
- 04
- BLOCK DIAGRAM - BMC
- 40
- JTAG_XDS200_3
- 05
- BLOCK DIAGRAM - XDS200
- 41
- JTAG_XDS200_4
- 06
- POWER FLOW DIAGRAM
- 42
- JTAG_XDS200_CPLD
- 07
- BOARD POWER SEQUENCE DIAGRAM
- 43
- XDS200 POWER
- 08
- I2C ADDRESS TABLE & McASP  CONFIGURATION
- 44
- BOARD MANAGEMENT CONTROL_1 (BMC)
- 09
- MCASP TREE
- 45
- BOARD MANAGEMENT CONTROL_2 (BMC)
- 10
- SoC CLOCK & RESET
- 46
- BOARD MANAGEMENT CONTROL_3 (BMC)
- 11
- SoC GPIO & RESERVED PINS
- 47
- PMIC POWER1
- 12
- SoC POWER1
- 48
- PMIC POWER2
- 13
- SoC POWER2
- 49
- 12V DC IN, 5V  & DDR3 POWER GENERATION
- 14
- DDR3 DEVICES
- 50
- OVER VOLTAGE PROTECTION
- 15
- DDR3 ECC & TERMINATIONS
- 16
- QSPI, I2C EEPROM & SPI NOR FLASH
- 17
- EMMC FLASH
- 18
- NAND  FLASH & MICRO SD CARD
- 19
- HDMI OR LCD MUX
- 20
- LCD & TOUCH SCREEN CONNECTOR
- 21
- HDMI TRANSMITTER
- 22
- AUDIO CODEC
- 23
- MCASP2 BUFFERS FOR COM8 , HDMI& AUDIO CODEC
- 24
- ETHERNET PHY
- 25
- PCIE x1 CONNECTOR
- 26
- USB DUAL ROLE & HOST
- 27
- UART0 & UART1
- 28
- UART2
- 29
- COM8 CONNECTOR
- 30
- MLB CONNECTOR
- 31
- DCAN
- 32
- McASP & AUDIO EXPANSION CONNECTOR
- 33
- SERIAL & EHRPWM EXPANSION CONNECTOR
- 34
- SERIAL CONTROL INTERFACES & I/O EXPANDER
- 35
- CLOCK DISTRIBUTION 1
- 36
- CLOCK DISTRIBUTION 2
sheet 3
- REVISION HISTORY
- VER #
- DATE
- DESCRIPTION OF CHANGES
- AUTHOR
- 12th  OCT 2015
- QSPI Buffer Removed (U148,C823,R916) ,R463 Mounted
  Over Voltage Protection Circuit Added in Page 50
- Mistral Design Team
- 0.1
- AA19,AB19,Y20,W19,D2,L2,G3,F18,H2,AA18,Y19,Y14,H5 and M5
  balls of the processor renamed
- 0.2
- 19th  OCT 2015
- R737 added
- Mistral Design Team
- R176,R184,R191,R198 changed to pull down
- R197,R190,R183,R175 changed to pull up
- R927 added b/w SOC and BMC
  Net "SOC_BAWCLKSEL" renamed as "RSV6_TOGGLE"
- 0.3
- 28th  OCT 2015
- Mistral Design Team
- Nets  BAW_ATEST, VDDA_BAW, VDD18_BAW are
  renamed as RSV7_ATEST, VDDA_0V9 ,VDD18_1V8
- 0.4
- 29th  OCT 2015
- Mistral Design Team
- "M5" & "H5" pins of processor moved to corresponding power domain symbol parts
  " M5 " pin of processor  tied directly to CVDD1
  FB18,C186,C526   Removed
  Tittle block updated as per customer request
- 0.5
- 4th  NOV 2015
- Mistral Design Team
- U142 replaced with TXS0108EPWR
  R58 made DNI
- 0.6
- 11th  NOV 2015
- Mistral Design Team
- 0.7
- 16th  NOV 2015
- R769 R562,R764 are made DNI due to internal pull up/down in TPD12S016
- Mistral Design Team
- 0.8
- 8th  DEC 2015
- Customer comments updated
- Mistral Design Team
- Beta ECR/ECN implemented
  Baselined schematics
- 1.0
- 11th  DEC 2015
- Mistral Design Team
- R374 and R370 mounted
- 1.1
- 18th  JAN 2016
- Mistral Design Team
- 1.2
- 4th MAR 2016
- R431 and R442 value changed to 200E
- Mistral Design Team
- 1.3
- 23rd MAR 2016
- VCNTL[0:5] pin names of U1-32 renamed as RSV[13:18]
- Mistral Design Team
- 1.4
- 28th MAR 2016
- Hided VCNTL[0:5] net labels of U1-32
- Mistral Design Team
- 1.5
- 12th APR 2016
- SOC pin names updated as per datasheet ' SPRS932A-DECEMBER 2015-REVISED
   FEBRUARY 2016 '
- Mistral Design Team
sheet 4
- BLOCK DIAGRAM - K2GEVM
sheet 5
- BLOCK DIAGRAM -  BMC
- VCC12V0_DC_IN
- +3.3V
- DC_DC
  TPS54429ERSAR
- VCC12V0_DC_IN
- VCC3V3_BMC
- VCC12V0_DC_IN
- +5V
- EN
- DC-DC
  [LM22675]
- DC_DC
  TPS54429ERSAR
- PMIC
- EN
- I2C2
- I2C1
- BUFFER
- I2C0
- I2C0
- LCD 128x 32
  NHD-C12832A1Z-NSW-BBW-3V3
- SPI1
- 5 PIN
  HDR
- BUFFER
- INA226 X 5
- 66AK2G02
    SoC
- OPTIONAL
- 4 PIN
  HDR
- UART0
- MAX3221
- 4
- DIP
  SWITCH
- GPIOs
- BMC
  [TM4C129XNCZAD]
- Mini USB
   Conn
- CP2105
- 2
- 16
- BOOT MODE SIGNALS
- LED
- ISOLATOR
- GPIOs
- DSS[8:23]
- UART1
- MUX/
  BUFFER
- UART2
- SPI0
- CDCM6208V2RGZT
- INT1
- BMC_INT
- INT
- ISOLATOR
- SoC_INT
- ISOLATOR
     X 3
- JTAG lines
- JTAG 14 PIN
  CONN
- 23
- JTAG_RST
- SOC, DEVICES
  RESET & CTRL
  SIGNALS
- GPIOs
- BMC_RESETn
- GPIOs
- 5
- PUSH
  BUTTON X 6
sheet 6
- BLOCK DIAGRAM -  XDS200
sheet 7
- POWER FLOW DIAGRAM
- OVP CKT
- VCC12V0_MLB
  +12V
- VCC12V0
  +12V
  1243mA
- VCC12V0_DC_IN
  +12V
  1679mA
- VCC3V3_DCIN
- VCC12V0_DC_IN
  +12V
  310mA
- VCC12V0_DC_IN
  +12V
  1160mA
- VCC12V0_AUD_EXP
  +12V
  750mA
- DC IN
  +12V
  7.6A
- LED
- VCC12V0_PCIE
  +12V
  2000mA
- PMIC_GPIO2
- 5V_EN
- EN
- AUDIO EXPANSION CONNECTOR
- TPS54429
- EN
- EN
- TPS54620RGY
- LM22675MR
- PCIE CONNECTOR
- 3300mA
- VCC3V3_BMC
  +3.3V
  924mA
- 370mA
- VCC5V0_DCDC
  +5V
  4741mA
- LED
- MLB CONNECTOR
- DCAN R1Z-3.305
        x2
- 400mA
- BOARD MANAGEMENT
  CONTROLLER( BMC)
  TM4C129XNCZADI3
- EN
- EN
- TPS79601DRBR
- LED
- EN
- TPS650006RTET
- TPS71712
- TPS61081
- LP3985IM5-3.0
- VCC_VBUS
  _XDS
- VCC3V3
- VCC3V3
- LED x 3
- VCOM_BAT
  1000mA
- VCC12V0_DC_IN
  +12V
  380mA
- VCC3V0_BMC_LCD
  +3V
  35mA
- VCC12V0_DC_IN
  +12V
  780mA
- VCC1V2
  +1.2V
  60mA
- VLED+
  +19.2V
  40mA
- VCC1V2
  _XDS
  +1.2V
  38mA
- VCC1V8
  _XDS
  +1.8V
  18.3mA
- VCC3V3
  _XDS
  +3.3V
  365mA
- SPI FLASH
  IS25CD010-JNLE
- PMIC_VIO
- COM8 CONN
- TPS54429
- EN
- HDMI TX
  SiI9022ACNU
- LCD BACKLIGHT
  NHD-4.3-480272EF-ATXL-CTP
- BMC DISPLAY
  NHD-C12832A1Z-NSW-BBW-3V3
- PROCESSOR
  AM1802
- +3.3V
  2554mA
- VCC5V0_DC_DC
- VCC3V3_DC_IN
- VCC5V0_USBx 1000mA
- SDRAM
  MT48LC4M16A2B4
  -75G
- USB1 LOAD SWITCH
  TPS2051BD
- PMIC  TPS659118
- TLV707085DQNT
- USB0 LOAD SWITCH
  TPS2051BD
- CPLD
  XC2C64A-5VQ44C
- SOC GPIO
- SD#
- LP2996A
- SPI EPROM
  N25Q128A13ESF40F
- MICRO SD CARD
- I2C EEPROM
  AT24CM01
- 12.288MHz
- VDDR_VTT
  +0.675V
  272mA
- VCC_DDR_VREF
  +0.675V
  0.05mA
- PROCESSOR
  AM1802
- AUDIO CODEC
  TLV320AIC3106IRGZT
- QSPI
  S25FL512SAGMFI011
- NAND FLASH
  MT29F2G16ABAFAWP:F
- VDD_DDR
  +1.35V
  1175mA
- CPLD
  XC2C64A-5VQ44C
- DDR3 x5
  MT41K512M8RH-125:E
- VCC1V8
  LDO2
  +1.8V
  276mA
- GPIO EXPANDER
  TCA9555RTWR
- LEDs x7
- Level Translator x3
  SN74AVC4T245PW
- PROCESSOR
  AM1802
- UART TO USB
   CP2105
- DCAN0 & 1
  ISO1050
- AUDIO CODEC
  TLV320AIC3106IRGZT
- EMMC16G-S100
- CS2000CP-CZZ
- DAC 8550IBDGKT
- TEMP SENSOR
  TMP102AIDRLT
- TCA9517DGKR
- AUD EXP
- INA226 x5
- AVDDA_XPLL
  DVDD18
  +1.8V
  300mA
- DVDD_DDR
  +1.35V
  284mA
- CVDD
  +0.9V
  4654mA
- CVDD1
  +0.9V
  464mA
- DDR_VREF
  +0.675V
  0.010mA
- DVDD33,
  VCC3V3
  +3.3V
  133mA
- LDO_PCIE
  /USB_CAP,
  +0.85V
  109mA
- Level Translator x3
  SN74AVC4T245PW
- CLOCK
  CDCM6208V2RGZT
- ETHERNET PHY
  KSZ9031RNXCA
- COM8 VBAT
      LDO
- RJ45 LEDs x2
- K2G PROCESSOR
   (66AK2G02)
- TOUCH SCREEN & LCD
- HDMI
  SiI9022ACNU
- DSS BUFFER x2
- EMMC16G-S100
- NOTE:
- REGULATORS
- DEVICES
- CLOCK
  CDCM6208V2RGZT
- LDO3_1V8,+1.8V,90mA
- Multiple powered
   device
sheet 8
- BOARD POWER UP SEQUENCE
sheet 9
- SoC I2C  ADDRESS TABLE
- BMC I2C ADDRESS TABLE
- I2C0 DEVICES
- 7 BIT ADDRESS
- I2C1 DEVICES
- 7 BIT ADDRESS
- BMC I2C0 DEVICES
- 7 BIT ADDRESS
- BMC I2C1 DEVICES
- 7 BIT ADDRESS
- EEPROM
- 0x50 (PAGE 0)
- 0x3B
- 0x40 : 3.3V
- PROCESSOR
- ALWAYS MASTER
- 0x51 (PAGE 1)
- HDMI TRANSMITTER
- 0x3F
- 0x41 : CVDD
- PMBUS
- BMC
- 0x0 (PROGRAMMABLE)
- 0x62
- 0x42 : CVDD1
- SERIAL EXPANSION CONNECTOR
- TBD
- AUDIO CODEC
- 0x1B
- 0x43 : 1.8V
- PCIe CONNECTOR
- TBD
- 0x70 (WRITE)
- 0x44 : DVDD_DDR
- TOUCH SCREEN
- 0x71 (READ)
- I/O EXPANDER
- 0x20
- I2C2 DEVICES
- 7 BIT ADDRESS
- TEMPERTURE SENSOR
- 0x48
- PMIC
- 0x2D (GENERAL PURPOSE)
  TBD
- MLB CONNECTOR
- TBD
- 0x12 (VOLTAGE SCALING)
  TBD
- AUDIO EXPANSION CONNECTOR
- 0x4A,0x4B,0x4C,0x4D
- CLOCK GENREATOR
  (CS2000CP-CZZ)
- 0x4F
- McASP  CONFIGURATION
- DEVICE MODE
- McASP PORT
- DEVICES
- DAC- PCM1690 x2
- SLAVE
- McASP0
- I2S HEADER
- MASTER
- McASP1
- ADC- PCM1865 x2
- SLAVE
- HDMI TRANSMITTER
  (DEFAULT)
- SLAVE
- McASP2
- AUDIO CODEC AIC3106
- DIR9001(DEFAULT)
- MASTER
- COM8
sheet 10
- AUDIO CODEC
- MCASP2_ACLKX
- BCLK
- MCASP2_FSX
- WCLK
- MCLK
- 12.288MHz
    OSC
- McASP DISTRIBUTION DIAGRAM
- MCASP2_AXR2
- BUFFER
- DIN
- DOUT
- MCLK
- HDM TXR
- SCK
- MUX 2
- M
  c
  A
  S
  P
  2
- WS
- SD[0:3]
- AUD_CLK
- MCASP2_AXR1
- AUD_FSYNC
- COM8
- BUFFER
- MCASP2_AXR4
- AUD_DIN
- AUD_DOUT
- MCASP2_AXR3
- 4
- DIR9001
- MCASP2_ACLKR
- BUFFER
- BCKO
- MCASP2_FSR
- LRCKO
- MCASP2_AXR5
- DOUT
- McASP2_AHCLKR
- SCKO
- A
  U
  D
  I
  O
  D
  A
  U
  G
  H
  T
  E
  R
  C
  A
  R
  D
- CS2000
- MCASP1_AXR0
- DOUT1
- MCASP1_AXR1
- DOUT2
- ADC0
- McASP1_AHCLKR
- SCKI
- McASP1_AFSR
- LRCK
- BUFFER
- McASP1_ACLKR
- BCK
- SCKI
- M
  c
  A
  S
  P
  1
- LRCK
- ADC1
- BCK
- MCASP1_AXR2
- DOUT1
- MCASP1_AXR3
- DOUT2
- 4
- MCASP1_AXR9
- AUDIO EXPANSION CONNECTOR
- Digital Audio OUT
- Coaxial RCA Conn
- McASP1_AHCLKX
- 4
- MCASP0_AXR[0:3]
- 4
- DIN[1:4]
- McASP0_ACLKX
- BCK
- DAC0
- McASP0_AFSX
- BUFFER
- LRCK
- McASP0_AHCLKX
- BUFFER
- SCKI
- MUTE
- MCASP0_AMUTE
- 4
- MUX
- MUTE
- MCASP0_AXR[4:7]
- DAC1
- SCKI
- M
  c
  A
  S
  P
  0
- BCK
- 4
- LRCK
- 4
- DIN[1:4]
- DNI
- McASP0_AHCLKR
- BUFFER
- MCLKOUT
- I2S HEADER
- McASP0_ACLKR
- BCLKOUT
- McASP0_AFSR
- LRCKOUT
- 4
- 4
- MCASP0_AXR[12:15]
- DOUT[0:3]
- 4
- MCLKIN
- BUFFER
- BCLKIN
- JUMPER
- OE#
- LRCKIN
- DIN[0:7]
- BUFFER
- JUMPER
- OE#
sheet 11
- SoC RESET
- POWER ON RESET
- FULL RESET
- WARM RESET
- SoC CLOCK
sheet 12
- SoC GPIOs
- RESERVED PINS
